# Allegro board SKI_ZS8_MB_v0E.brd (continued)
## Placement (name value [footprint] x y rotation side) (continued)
PR73  63.4k/f_4  [RC0402]  147.95 7.37 180 top
PR74  *short_6  [SHORT0603]  143.13 6.98 90 top
PR75  *4.7_6  [RC0603]  131.06 6.86 90 top
PR76  36.5k/f_4  [RC0402]  197.08 103.02 90 bottom
PR77  665k/f_4  [RC0402]  198.15 103.05 90 bottom
PR78  *90.9k/f_4  [RC0402]  199.24 103.07 90 bottom
PR79  2m/f_4  [RC0402]  204.34 102.87 0 bottom
PR80  30k/f_4  [RC0402]  200.38 102.77 270 bottom
PR81  39k/f_4  [RC0402]  201.42 102.36 270 bottom
PR82  10k/f_4  [RC0402]  204.34 101.73 0 bottom
PR83  *short_4  [SHORT0402]  194.92 101.7 270 bottom
PR84  100k/f_4  [RC0402]  195.94 101.7 270 bottom
PR85  20k/f_4  [RC0402]  197.08 100.91 270 bottom
PR86  100k/f_4  [RC0402]  198.17 101 270 bottom
PR87  150k/f_4  [RC0402]  199.26 100.99 270 bottom
PR88  2m/f_4  [RC0402]  200.41 100.69 90 bottom
PR89  374k/f_4  [RC0402]  201.42 100.25 270 bottom
PR90  *0_4  [RC0402]  195.45 100.08 0 bottom
PR91  16.9k/f_4  [RC0402]  204.88 100.08 90 bottom
PR92  *100k/f_4  [RC0402]  195.45 99.06 0 bottom
PR93  22_8  [RC0805]  66.93 98.93 180 bottom
PR94  *short_4  [SHORT0402]  204.47 98.4 0 bottom
PR95  *100k/f_4  [RC0402]  195.45 98.04 0 bottom
PR96  *10_4  [RC0402]  206.65 97.67 0 bottom
PR97  *short_4  [SHORT0402]  204.47 97.33 0 bottom
PR98  *short_4  [SHORT0402]  204.34 96.27 0 bottom
PR99  100k/f_4  [RC0402]  195.33 95.83 0 bottom
PR100  *short_4  [SHORT0402]  204.34 95.15 0 bottom
PR101  22_8  [RC0805]  66.93 95 180 bottom
PR102  22_8  [RC0805]  80.9 94.87 270 bottom
PR103  *short_4  [SHORT0402]  195.33 94.67 0 bottom
PR104  *10_4  [RC0402]  205.89 93.5 90 bottom
PR105  1_6  [RC0603]  195.07 93.47 0 bottom
PR106  *100k/f_6  [RC0603]  74.17 92.84 180 bottom
PR107  4.99k/f_4  [RC0402]  201.55 92.58 180 bottom
PR108  *short_4  [SHORT0402]  197.23 91.95 90 bottom
PR109  *short_4  [SHORT0402]  198.37 91.95 90 bottom
PR110  *short_4  [SHORT0402]  199.52 91.95 90 bottom
PR111  10k/f_4  [RC0402]  201.55 91.57 0 bottom
PR112  4.75k/f_4  [RC0402]  201.55 90.55 180 bottom
PR113  1m_4  [RC0402]  74.42 90.3 180 bottom
PR114  1m_4  [RC0402]  69.98 89.79 0 bottom
PR115  130/f_4  [RC0402]  197.23 89.79 270 bottom
PR116  *75/f_4  [RC0402]  198.37 89.79 270 bottom
PR117  56_4  [RC0402]  199.52 89.79 270 bottom
PR118  *1m_4  [RC0402]  73.85 88.71 90 bottom
PR119  1m_4  [RC0402]  69.98 88.65 180 bottom
PR120  30k/f_4  [RC0402]  66.67 88.27 90 bottom
PR121  *100k_4  [RC0402]  73.85 86.68 270 bottom
PR122  *0_4  [RC0402]  74.87 86.68 90 bottom
PR123  34k/f_4  [RC0402]  67.18 86.61 180 bottom
PR124  100k_4  [RC0402]  56.13 86.11 0 bottom
PR125  *100k_4  [RC0402]  74.36 85.16 0 bottom
PR126  *short_4  [SHORT0402]  56.13 84.96 0 bottom
PR127  *100k_4  [RC0402]  60.58 84.96 180 bottom
PR128  *1m_4  [RC0402]  69.85 83.06 90 bottom
PR129  *1m_4  [RC0402]  70.99 83.06 270 bottom
PR130  *22_8  [RC0805]  73.47 82.62 180 bottom
PR131  *short_8  [SHORT0805]  74.42 76.96 90 bottom
PR132  1.47k/f_4  [RC0402]  163.96 67.69 90 bottom
PR133  200k/f_4  [RC0402]  165.1 67.69 90 bottom
PR134  200k/f_4  [RC0402]  166.24 67.69 270 bottom
PR135  *4.7_6  [RC0603]  44.3 64.16 90 bottom
PR136  *4.7_6  [RC0603]  65.91 63.25 90 bottom
PR137  82k/f_4  [RC0402]  42.75 63.37 90 bottom
PR138  *4.7_6  [RC0603]  56.69 62.84 90 bottom
PR139  11k/f_4  [RC0402]  42.29 61.72 0 bottom
PR140  *short_6  [SHORT0603]  48.69 60.76 90 bottom
PR141  200k_6  [RC0603]  161.04 60.33 270 bottom
PR142  *short_6  [SHORT0603]  54.76 59.36 180 bottom
PR143  *short_6  [SHORT0603]  161.29 56.64 270 bottom
PR144  1m_6  [RC0603]  158.62 53.09 180 bottom
PR145  22_8  [RC0805]  50.8 48.34 90 bottom
PR146  *short_4  [SHORT0402]  179.96 47.62 0 bottom
PR147  *short_4  [SHORT0402]  65.53 47.12 90 bottom
PR148  10k/f_4  [RC0402]  66.55 47.12 90 bottom
PR149  5.1k/f_4  [RC0402]  67.56 47.12 90 bottom
PR150  0.01/f_0612  [RC3216]  183.13 46.99 180 bottom
PR151  *short_4  [SHORT0402]  179.96 46.48 0 bottom
PR152  *100k_4  [RC0402]  80.01 37.34 90 bottom
PR153  34k/f_4  [RC0402]  82.17 25.53 90 bottom
PR154  33k/f_4  [RC0402]  131.32 15.49 90 bottom
PR155  100k_4  [RC0402]  153.8 13.97 180 bottom
PR156  10k_4  [RC0402]  147.45 13.21 270 bottom
PR157  *0_4  [RC0402]  148.46 13.21 270 bottom
PR158  100k/f_4  [RC0402]  149.48 13.21 90 bottom
PR159  0.01/f_0612  [RC3216]  123.06 12.06 0 bottom
PR160  100k_4  [RC0402]  157.35 12.06 270 bottom
PR161  *0_4  [RC0402]  154.56 10.16 180 bottom
PR162  *short_4  [SHORT0402]  151.41 10.13 180 bottom
PR163  *short_6  [SHORT0603]  142.54 9.4 180 bottom
PR164  *short_4  [SHORT0402]  151.41 9.12 180 bottom
PR165  *short_4  [SHORT0402]  153.67 8.64 90 bottom
PR166  *10k_4  [RC0402]  154.69 8.64 90 bottom
PR167  316k/f_4  [RC0402]  151.41 8.1 180 bottom
PR168  100k/f_4  [RC0402]  151.41 7.06 0 bottom
PR169  *100k_4  [RC0402]  151.41 6.05 0 bottom
PR170  10k_4  [RC0402]  149.35 5.08 180 bottom
PR171  10_6  [RC0603]  146.43 4.7 270 bottom
PR172  7.5_6  [RC0603]  147.7 4.7 270 bottom
PR173  *short_4  [SHORT0402]  142.62 3.94 180 bottom
PR174  *short_4  [SHORT0402]  142.62 2.92 180 bottom
PR175  *short_8  [SHORT0805]  86.55 26.23 0 bottom
PR176  *short_4  [SHORT0402]  150.28 14.87 180 bottom
PU1  csd97374cq4m  [SON8-4_5X3_5-5-9P-SMT]  185.28 98.26 0 top
PU2  nb671gq-z  [QFN14-3X3-4-16P]  46.08 62.43 90 top
PU3  nb670gq-z  [QFN14-3X3-4-16P]  55.27 60.76 90 top
PU4  tps51716rukr  [QFN20-3X3-4-26P]  195.28 60.76 90 top
PU5  tps51211dscr  [SON10-3X3-5-16P]  65.96 50.5 0 top
PU6  *cm1293a-04so  [SOT23-6-2_8-95-6P]  108.97 6.86 180 top
PU7  tps51624rsm  [QFN32-4X4-4-42P-1H]  199.62 96.29 0 bottom
PU8  g9661-25adjf12u  [SOP8-6-1_27-9P]  61.98 88.27 90 bottom
PU9  as393mtr-e1  [SOIC8-6-1_27]  164.59 62.23 0 bottom
PU10  g9661-25adjf12u  [SOP8-6-1_27-9P]  83.31 31.62 0 bottom
PU11  bq24737rgrr  [PVQFN20-3_5X3_5-5-25P]  147.45 9.14 0 bottom
Q1  fdv301n  [SOT23_213-3_3-2]  134.92 97.42 90 top
Q2  mmbt3904-7-f  [SOT23_213-3_3-2]  139.87 97.29 90 top
Q3  ap2331sa-7  [SOT23_213-3_3-2]  11.18 97.16 180 top
Q4  dtc144eu  [UMT_213-3-1_3]  24.32 83.99 270 top
Q5  2n7002dw  [SC70-2_1-65-6P]  20.07 93.09 270 top
Q6  bsn20  [SOT23_213-3_3-2]  12.45 89.66 270 top
Q7  bsn20  [SOT23_213-3_3-2]  16.13 89.66 270 top
Q8  *2n7002dw  [SC70-2_1-65-6P]  199.01 74.68 0 top
Q9  2n7002k  [SOT23_213-3_3-2]  13.59 73.63 0 top
Q10  *2n7002dw  [SC70-2_1-65-6P]  82.55 72.9 180 top
Q11  *2n7002dw  [SC70-2_1-65-6P]  82.55 70.1 180 top
Q12  mmbt3904  [SOT23_213-3_3-2]  208.15 63.88 270 top
Q13  *ao3413  [SOT23_213-3_3-2]  84.9 54.55 270 top
Q14  *2n7002k  [SOT23_213-3_3-2]  81.15 51.69 270 top
Q15  2n7002k  [SOT23_213-3_3-2]  28.19 33.15 0 top
Q16  2n7002k  [SOT23_213-3_3-2]  195.33 32.51 90 top
Q17  2n7002dw  [SC70-2_1-65-6P]  175.58 20.51 90 bottom
Q18  2n7002k  [SOT23_213-3_3-2]  11.57 89.15 0 bottom
Q19  ao3413  [SOT23_213-3_3-2]  199.26 82.3 180 bottom
Q20  2n7002k  [SOT23_213-3_3-2]  77.6 80.64 180 bottom
Q21  2n7002k  [SOT23_213-3_3-2]  199.26 78.61 0 bottom
Q22  *2n7002k  [SOT23_213-3_3-2]  185.67 54.86 270 bottom
Q23  2n7002dw  [SC70-2_1-65-6P]  32 27.3 180 bottom
Q24  2n7002k  [SOT23_213-3_3-2]  70.54 26.92 180 bottom
Q25  2n7002dw  [SC70-2_1-65-6P]  35.56 12.95 0 bottom
Q53  ao3413  [SOT23_213-3_3-2]  33.85 5.91 0 top
Q54  *dtc144eu  [UMT_213-3-1_3]  43.88 3.5 180 top
Q55  *dtc144eu  [UMT_213-3-1_3]  47.56 3.5 180 top
Q56  *2n7002k  [SOT23_213-3_3-2]  52.77 4 180 top
R1  *short_8  [SHORT0805]  95.38 100.46 180 top
R2  10k_4  [RC0402]  133.73 100.08 180 top
R3  1k_4  [RC0402]  137.41 98.81 90 top
R4  *0_4  [RC0402]  162.43 98.81 90 top
R5  *1k_4  [RC0402]  163.58 98.81 90 top
R6  *1k_4  [RC0402]  164.72 98.81 90 top
R7  *short_4  [SHORT0402]  127.42 98.31 90 top
R8  10k_4  [RC0402]  128.69 98.31 90 top
R9  *0_4  [RC0402]  123.36 97.67 180 top
R10  *short_8  [SHORT0805]  94.61 97.66 90 top
R11  *short_8  [SHORT0805]  96.65 97.66 270 top
R12  1k_4  [RC0402]  137.41 96.77 90 top
R13  0_4  [RC0402]  123.36 96.53 180 top
R14  10k_4  [RC0402]  18.87 96.16 0 top
R15  *10k_4  [RC0402]  148.34 96.14 90 top
R16  *0_4  [RC0402]  123.36 95.39 180 top
R17  *10k_4  [RC0402]  136.27 94.36 90 top
R18  10k_4  [RC0402]  96.27 93.98 90 top
R19  10k_4  [RC0402]  97.41 93.99 90 top
R20  *1k_4  [RC0402]  98.55 93.98 270 top
R21  10k_4  [RC0402]  99.69 93.98 90 top
R22  10k_4  [RC0402]  100.71 93.98 90 top
R23  *10k_4  [RC0402]  101.73 93.98 90 top
R24  2.2k_4  [RC0402]  93.85 93.71 90 top
R25  2.2k_4  [RC0402]  95.12 93.71 90 top
R26  *short_4  [SHORT0402]  140.59 93.34 90 top
R27  2.2k_4  [RC0402]  12.57 92.96 270 top
R28  10k_4  [RC0402]  137.54 92.96 90 top
R29  2.2k_4  [RC0402]  17.53 92.71 270 top
R30  51_4  [RC0402]  142.75 92.58 270 top
R31  *short_4  [SHORT0402]  143.89 92.58 270 top
R32  10k_4  [RC0402]  120.89 91.2 90 top
R33  10k_4  [RC0402]  122.03 91.2 90 top
R34  *0_4  [RC0402]  124.8 91.85 180 top
R35  *0_4  [RC0402]  124.8 90.65 180 top
R36  *0_4  [RC0402]  132.97 91.19 270 top
R37  10k_4  [RC0402]  136.14 91.19 270 top
R38  100/f_4  [RC0402]  140.08 91.19 90 top
R39  100/f_4  [RC0402]  141.48 91.19 270 top
R40  10k_4  [RC0402]  19.5 90.24 0 top
R41  1m_4  [RC0402]  114.67 90.97 180 top
R42  150_4  [RC0402]  143.26 90.93 0 top
R43  3.01k/f_4  [RC0402]  116.19 90.56 270 top
R44  *short_4  [SHORT0402]  117.36 90.56 270 top
R45  100k_4  [RC0402]  21.28 89.6 90 top
R46  10k_4  [RC0402]  82.62 87.95 90 top
R47  10k_4  [RC0402]  83.63 87.95 90 top
R48  10k_4  [RC0402]  84.65 87.95 90 top
R49  10k_4  [RC0402]  85.66 87.95 90 top
R50  10k_4  [RC0402]  86.68 87.95 90 top
R51  10k_4  [RC0402]  87.7 87.95 90 top
R52  2.2k_4  [RC0402]  13.84 87 180 top
R53  2.2k_4  [RC0402]  16.51 87 0 top
R54  *51_4  [RC0402]  160.91 86.74 270 top
R55  *0_4  [RC0402]  161.93 86.74 270 top
R56  *1k_4  [RC0402]  162.94 86.74 270 top
R57  *1k_4  [RC0402]  163.96 86.74 270 top
R58  10k_4  [RC0402]  80.71 85.79 180 top
R59  *100/f_4  [RC0402]  12.32 84.96 90 top
R60  *10k_4  [RC0402]  80.71 84.78 180 top
R61  10k_4  [RC0402]  83.38 84.78 0 top
R62  10k_4  [RC0402]  86.05 84.78 0 top
R63  *10k_4  [RC0402]  80.71 83.76 180 top
R64  10k_4  [RC0402]  83.38 83.76 0 top
R65  10k_4  [RC0402]  86.05 83.76 0 top
R66  10k_4  [RC0402]  88.71 83.76 180 top
R67  *0_8  [RC0805]  199.2 81.73 0 top
R68  56_4  [RC0402]  143.26 82.8 180 top
R69  62_4  [RC0402]  145.54 82.8 0 top
R70  *10k_4  [RC0402]  80.71 82.74 180 top
R71  10k_4  [RC0402]  83.38 82.74 180 top
R72  10k_4  [RC0402]  86.05 82.74 180 top
R73  *100/f_4  [RC0402]  12.32 82.55 90 top
R74  10k_4  [RC0402]  80.58 81.73 0 top
R75  *short_4  [SHORT0402]  83.38 81.73 0 top
R76  10k_4  [RC0402]  85.79 81.73 180 top
R77  *short_4  [SHORT0402]  143.38 81.66 180 top
R78  130/f_4  [RC0402]  145.54 81.66 180 top
R79  100k_4  [RC0402]  199.39 83.44 0 top
R80  st@10k_4  [RC0402]  80.46 80.71 180 top
R81  10k_4  [RC0402]  83.38 80.71 0 top
R82  10k_4  [RC0402]  85.41 80.71 180 top
R83  43_4  [RC0402]  143.26 80.52 180 top
R84  75_4  [RC0402]  145.54 80.52 180 top
R85  *0_4  [RC0402]  78.93 80.46 270 top
R86  *0_4  [RC0402]  80.84 79.7 180 top
R87  st@10k_4  [RC0402]  83.38 79.7 180 top
R88  *1k_4  [RC0402]  86.05 79.7 0 top
R89  100k_4  [RC0402]  21.21 79.63 270 top
R90  *short_6  [SHORT0603]  199.84 79.57 0 top
R91  *short_4  [SHORT0402]  143.64 79.5 180 top
R92  *100/f_4  [RC0402]  12.32 78.99 90 top
R93  10k_4  [RC0402]  80.84 78.68 0 top
R94  10k_4  [RC0402]  83.38 78.68 180 top
R95  10k_4  [RC0402]  85.92 78.68 180 top
R96  *1k_4  [RC0402]  142.11 78.36 180 top
R97  *st@10k_4  [RC0402]  80.84 77.66 180 top
R98  10k_4  [RC0402]  83.38 77.66 180 top
R99  10k_4  [RC0402]  85.92 77.66 0 top
R100  *1k_4  [RC0402]  142.88 77.34 180 top
R101  *short_6  [SHORT0603]  202.89 78.68 0 top
R102  *short_8  [SHORT0805]  20.19 77.22 180 top
R103  1k_4  [RC0402]  145.03 77.22 0 top
R104  *1k_4  [RC0402]  147.19 77.22 180 top
R105  *1k_4  [RC0402]  149.3 76.9 0 top
R106  *1k_4  [RC0402]  151.46 76.9 180 top
R107  *0_4  [RC0402]  88.08 77.16 90 top
R108  0_4  [RC0402]  89.09 77.16 90 top
R109  *0_4  [RC0402]  85.92 76.65 180 top
R110  *100/f_4  [RC0402]  12.32 76.45 90 top
R111  49.9/f_4  [RC0402]  142.11 76.07 180 top
R112  *1k_4  [RC0402]  144.27 76.07 180 top
R113  10k_4  [RC0402]  85.92 75.63 180 top
R114  10k_4  [RC0402]  88.71 75.63 180 top
R115  *0_4  [RC0402]  81.47 75.38 0 top
R116  2.2k_4  [RC0402]  84.14 75.25 90 top
R117  51_4  [RC0402]  149.35 74.8 0 top
R118  *51_4  [RC0402]  151.51 74.8 180 top
R119  *0_4  [RC0402]  85.92 74.62 0 top
R120  *0_4  [RC0402]  88.71 74.62 0 top
R121  *4.7k_4  [RC0402]  79.38 73.79 0 top
R122  51_4  [RC0402]  142.11 73.79 0 top
R123  51_4  [RC0402]  144.27 73.79 180 top
R124  51_4  [RC0402]  146.43 73.79 0 top
R125  *1k_4  [RC0402]  148.59 73.79 180 top
R126  2.2k_4  [RC0402]  85.66 73.47 0 top
R127  10k_4  [RC0402]  88.71 73.6 180 top
R128  100k_4  [RC0402]  31.75 78.93 180 top
R129  *100k_4  [RC0402]  33.91 78.93 0 top
R130  2.2k_4  [RC0402]  79.38 72.39 180 top
R131  *4.7k_4  [RC0402]  85.66 72.08 180 top
R132  10k_4  [RC0402]  88.71 72.58 180 top
R133  0_4  [RC0402]  21.01 70.87 180 top
R134  *2.2k_4  [RC0402]  78.99 70.61 180 top
R135  0_4  [RC0402]  85.85 70.61 0 top
R136  *10k_4  [RC0402]  88.39 70.48 180 top
R137  *100k_4  [RC0402]  31.75 77.66 180 top
R138  100k_4  [RC0402]  33.91 77.66 0 top
R139  0_4  [RC0402]  78.99 69.6 180 top
R140  *2.2k_4  [RC0402]  85.85 69.6 0 top
R141  10k_4  [RC0402]  88.39 69.47 180 top
R142  220k/f_4  [RC0402]  149.1 69.09 270 top
R143  *short_8  [SHORT0805]  24.13 69.47 0 top
R144  10k_4  [RC0402]  83.44 68.2 180 top
R145  2.2k_4  [RC0402]  85.85 68.2 180 top
R146  10k_4  [RC0402]  87.91 68.2 180 top
R147  *51_4  [RC0402]  141.61 67.94 90 top
R148  *10k_4  [RC0402]  83.44 67.18 180 top
R149  10k_4  [RC0402]  85.85 67.18 180 top
R150  *short_8  [SHORT0805]  24.13 67.31 0 top
R151  *10k_4  [RC0402]  83.44 66.17 180 top
R152  10k_4  [RC0402]  85.85 66.17 180 top
R153  10k_4  [RC0402]  88.01 66.17 180 top
R154  *short_4  [SHORT0402]  185.42 65.91 270 top
R155  10k_4  [RC0402]  85.85 65.15 180 top
R156  10k_4  [RC0402]  88.01 65.15 180 top
R157  10k_4  [RC0402]  204.47 65.15 90 top
R158  10k_4  [RC0402]  205.61 65.15 270 top
R159  *short_8  [SHORT0805]  202.82 64.52 270 top
R160  *10k_4  [RC0402]  83.44 64.01 180 top
R161  10k_4  [RC0402]  85.85 64.01 180 top
R163  *0_4  [RC0402]  20.41 61.97 180 top
R164  10k_4  [RC0402]  85.85 62.86 180 top
R165  1k_4  [RC0402]  204.47 62.86 90 top
R166  *0_4  [RC0402]  83.44 61.59 0 top
R167  10k_4  [RC0402]  85.85 61.59 180 top
R168  *short_4  [SHORT0402]  23.13 61.41 90 top
R169  100k_4  [RC0402]  97.1 60.81 180 top
R171  *0_4  [RC0402]  20.41 60.95 180 top
R172  10k_4  [RC0402]  97.1 59.79 180 top
R173  10m_4  [RC0402]  90.3 59.69 0 top
R174  20k/f_4  [RC0402]  94.11 59.69 0 top
R175  15_4  [RC0402]  71.12 59.56 270 top
R176  15_4  [RC0402]  73.41 59.56 270 top
R177  *1k_4  [RC0402]  74.55 59.56 270 top
R178  330k_4  [RC0402]  98.68 58.93 90 top
R179  330k_4  [RC0402]  99.69 58.93 90 top
R180  33_4  [RC0402]  100.71 58.93 90 top
R181  0_4  [RC0402]  96.65 56.13 90 top
R182  *short_4  [SHORT0402]  97.79 56.13 90 top
R183  *0_4  [RC0402]  98.81 56.13 90 top
R184  0_4  [RC0402]  99.82 56.13 90 top
R185  33_4  [RC0402]  101.85 56.13 90 top
R186  49.9/f_4  [RC0402]  103.33 56.06 270 top
R187  49.9/f_4  [RC0402]  104.34 56.06 270 top
R188  tpm@22_4  [RC0402]  105.56 56.03 270 top
R189  100k_4  [RC0402]  90.93 55.5 180 top
R190  *0_4  [RC0402]  96.65 53.85 270 top
R191  100k_4  [RC0402]  99.82 53.72 270 top
R192  *10k_4  [RC0402]  90.93 53.34 180 top
R193  *0_4  [RC0402]  90.93 52.32 180 top
R194  *0_6  [RC0603]  36.7 44.2 180 top
R195  *0_6  [RC0603]  39.37 44.2 180 top
R196  *0_6  [RC0603]  34.04 42.93 180 top
R197  *0_6  [RC0603]  36.7 42.93 180 top
R198  *0_6  [RC0603]  39.37 42.93 180 top
R199  *short_4  [SHORT0402]  202.63 40.96 180 top
R200  *short_4  [SHORT0402]  21.34 42.55 0 top
R201  *10k_4  [RC0402]  202.63 39.82 180 top
R202  *short_4  [SHORT0402]  179.96 40.26 90 top
R203  2.2_6  [RC0603]  47.5 39.62 270 top
R204  240/f_4  [RC0402]  146.05 39.27 180 top
R205  *short_4  [SHORT0402]  202.63 37.53 180 top
R206  240/f_4  [RC0402]  107.87 38.99 90 top
R207  80.6/f_4  [RC0402]  144.9 37.51 180 top
R208  *short_4  [SHORT0402]  60.58 37.34 0 top
R209  80.6/f_4  [RC0402]  107.7 37.34 0 top
R210  10k_4  [RC0402]  202.63 36.39 0 top
R211  80.6/f_4  [RC0402]  144.9 36.5 180 top
R212  80.6/f_4  [RC0402]  107.7 36.2 0 top
R213  *short_4  [SHORT0402]  179.96 35.81 90 top
R214  100k_4  [RC0402]  27.43 35.69 180 top
R215  80.6/f_4  [RC0402]  144.9 35.48 180 top
R216  80.6/f_4  [RC0402]  107.7 35.05 0 top
R217  240/f_4  [RC0402]  127.64 34.92 270 top
R218  240/f_4  [RC0402]  146.55 34.84 270 top
R219  240/f_4  [RC0402]  89.41 34.34 180 top
R220  *short_4  [SHORT0402]  21.59 33.91 180 top
R221  240/f_4  [RC0402]  108.97 33.53 90 top
R222  240/f_4  [RC0402]  126.82 33.32 180 top
R223  240/f_4  [RC0402]  89.41 33.19 180 top
R224  *short_4  [SHORT0402]  77.57 33.15 270 top
R225  *short_4  [SHORT0402]  78.61 33.15 270 top
R226  *100k_4  [RC0402]  32.13 32.51 270 top
R227  1m_4  [RC0402]  197.81 32.2 270 top
R228  *short_4  [SHORT0402]  60.45 32.26 0 top
R229  0_4  [RC0402]  194.76 29.66 0 top
R230  *short_4  [SHORT0402]  29.59 30.1 270 top
R231  54.9/f_4  [RC0402]  129.54 29.38 270 top
R232  54.9/f_4  [RC0402]  130.68 29.38 270 top
R233  54.9/f_4  [RC0402]  131.82 29.38 270 top
R234  54.9/f_4  [RC0402]  132.97 29.38 270 top
R235  54.9/f_4  [RC0402]  134.11 29.38 270 top
R236  37.4/f_4  [RC0402]  135.25 29.38 270 top
R237  37.4/f_4  [RC0402]  136.27 29.38 270 top
R238  80.6/f_4  [RC0402]  137.28 29.38 270 top
R239  80.6/f_4  [RC0402]  138.3 29.38 270 top
R240  54.9/f_4  [RC0402]  139.32 29.38 270 top
R241  54.9/f_4  [RC0402]  140.33 29.38 270 top
R242  54.9/f_4  [RC0402]  141.35 29.38 270 top
R243  54.9/f_4  [RC0402]  142.36 29.38 270 top
R244  54.9/f_4  [RC0402]  143.38 29.38 270 top
R245  54.9/f_4  [RC0402]  147.19 29.38 270 top
R246  54.9/f_4  [RC0402]  148.21 29.38 270 top
R247  54.9/f_4  [RC0402]  149.35 29.38 270 top
R248  54.9/f_4  [RC0402]  150.49 29.38 270 top
R249  54.9/f_4  [RC0402]  151.63 29.38 270 top
R250  37.4/f_4  [RC0402]  152.78 29.38 270 top
R251  37.4/f_4  [RC0402]  153.79 29.38 270 top
R252  80.6/f_4  [RC0402]  154.81 29.38 270 top
R253  80.6/f_4  [RC0402]  155.83 29.38 270 top
R254  54.9/f_4  [RC0402]  156.84 29.38 270 top
R255  54.9/f_4  [RC0402]  157.86 29.38 270 top
R256  54.9/f_4  [RC0402]  158.87 29.38 270 top
R257  54.9/f_4  [RC0402]  159.89 29.38 270 top
R258  54.9/f_4  [RC0402]  160.91 29.38 270 top
R259  54.9/f_4  [RC0402]  92.72 29.26 270 top
R260  54.9/f_4  [RC0402]  93.86 29.26 270 top
R261  54.9/f_4  [RC0402]  95 29.26 270 top
R262  54.9/f_4  [RC0402]  96.15 29.26 270 top
R263  54.9/f_4  [RC0402]  97.29 29.26 270 top
R264  37.4/f_4  [RC0402]  98.43 29.26 270 top
R265  37.4/f_4  [RC0402]  99.45 29.26 270 top
R266  80.6/f_4  [RC0402]  100.46 29.26 270 top
R267  80.6/f_4  [RC0402]  101.48 29.26 270 top
R268  54.9/f_4  [RC0402]  102.5 29.26 270 top
R269  54.9/f_4  [RC0402]  103.51 29.26 270 top
R270  54.9/f_4  [RC0402]  104.53 29.26 270 top
R271  54.9/f_4  [RC0402]  105.54 29.26 270 top
R272  54.9/f_4  [RC0402]  106.56 29.26 270 top
R273  54.9/f_4  [RC0402]  110.07 29.26 270 top
R274  54.9/f_4  [RC0402]  111.08 29.26 270 top
R275  54.9/f_4  [RC0402]  112.23 29.26 270 top
R276  54.9/f_4  [RC0402]  113.37 29.26 270 top
R277  54.9/f_4  [RC0402]  114.51 29.26 270 top
R278  37.4/f_4  [RC0402]  115.65 29.26 270 top
R279  37.4/f_4  [RC0402]  116.67 29.26 270 top
R280  80.6/f_4  [RC0402]  117.69 29.26 270 top
R281  80.6/f_4  [RC0402]  118.7 29.26 270 top
R282  54.9/f_4  [RC0402]  119.72 29.26 270 top
R283  54.9/f_4  [RC0402]  120.73 29.26 270 top
R284  54.9/f_4  [RC0402]  121.75 29.26 270 top
R285  54.9/f_4  [RC0402]  122.77 29.26 270 top
R286  54.9/f_4  [RC0402]  123.78 29.26 270 top
R287  47k_4  [RC0402]  40.89 29.08 90 top
R288  *short_4  [SHORT0402]  24 28.96 270 top
R289  *short_4  [SHORT0402]  16.96 28.77 270 top
R290  *short_8  [SHORT0805]  202.25 27.63 0 top
R291  4.7k_4  [RC0402]  40.51 27.43 180 top
R292  20k/f_4  [RC0402]  35.56 26.8 90 top
R293  39.2k/f_4  [RC0402]  36.7 26.8 90 top
R294  *short_6  [SHORT0603]  67.87 23.34 0 top
R295  10k_4  [RC0402]  41.78 23.24 0 top
R296  *1k_4  [RC0402]  22.23 21.97 270 top
R297  4.7k_4  [RC0402]  27.3 21.97 180 top
R298  tpm@0_6  [RC0603]  68.58 21.72 0 top
R299  *tpm@4.7k_4  [RC0402]  73.02 21.34 270 top
R300  *tpm@0_4  [RC0402]  74.17 21.34 270 top
R301  *tpm@10k_4  [RC0402]  75.56 21.34 270 top
R302  4.7k_4  [RC0402]  27.3 20.95 180 top
R303  *tpm@0_6  [RC0603]  68.58 20.45 0 top
R304  *1k_4  [RC0402]  22.23 19.94 270 top
R305  56/f_4  [RC0402]  27.3 19.81 180 top
R308  *short_8  [SHORT0805]  201.87 21.4 270 top
R309  56/f_4  [RC0402]  27.3 18.67 180 top
R310  *10k_4  [RC0402]  39.37 16.76 90 top
R311  *0_4  [RC0402]  200.53 16.38 0 top
R312  *0_4  [RC0402]  200.53 15.11 0 top
R313  *short_6  [SHORT0603]  34.92 13.34 90 top
R314  *short_6  [SHORT0603]  36.32 13.34 90 top
R315  *short_4  [SHORT0402]  201.36 9.08 180 top
R316  *short_4  [SHORT0402]  22.23 11.81 90 top
R317  *short_6  [SHORT0603]  28.32 11.43 90 top
R318  *10k_4  [RC0402]  201.36 11.24 180 top
R319  *short_4  [SHORT0402]  201.36 10.23 180 top
R320  *short_4  [SHORT0402]  18.14 9.68 90 top
R321  *short_4  [SHORT0402]  6.35 9.27 90 top
R322  0_6  [RC0603]  19.05 7.24 180 top
R323  *0_6  [RC0603]  29.02 6.29 270 top
R325  *short_4  [SHORT0402]  37.91 6.54 90 top
R326  0_6  [RC0603]  19.05 5.84 180 top
R327  0_6  [RC0603]  19.05 4.57 180 top
R328  0_6  [RC0603]  19.05 3.17 180 top
R329  *0_6  [RC0603]  104.14 96.01 180 bottom
R330  10k_4  [RC0402]  92.96 94.61 180 bottom
R331  100k_4  [RC0402]  27.22 85.36 0 top
R332  *short_6  [SHORT0603]  90.3 94.08 180 bottom
R333  *short_6  [SHORT0603]  108.84 93.85 90 bottom
R334  10k_4  [RC0402]  92.96 93.6 180 bottom
R335  100k_4  [RC0402]  97.66 93.6 90 bottom
R336  3.01k/f_4  [RC0402]  105.18 93.6 90 bottom
R337  *short_4  [SHORT0402]  106.2 93.6 90 bottom
R338  8.2k_4  [RC0402]  107.57 93.6 270 bottom
R339  *short_6  [SHORT0603]  111 93.09 180 bottom
R340  0_4  [RC0402]  26.56 83.66 90 top
R341  0_4  [RC0402]  27.73 83.66 90 top
R342  3.01k/f_4  [RC0402]  114.3 92.08 180 bottom
R343  1m_4  [RC0402]  15.23 88.41 180 bottom
R344  10k_4  [RC0402]  82.62 87.95 90 bottom
R345  *1k_4  [RC0402]  83.63 87.95 270 bottom
R346  2.2k_4  [RC0402]  84.65 87.95 90 bottom
R347  2.2k_4  [RC0402]  85.66 87.95 90 bottom
R348  *short_4  [SHORT0402]  10.67 86.82 180 bottom
R349  20k_4  [RC0402]  13.97 86.69 0 bottom
R350  470_4  [RC0402]  14.1 85.6 0 bottom
R351  10k_4  [RC0402]  80.71 84.78 180 bottom
R352  10k_4  [RC0402]  83.38 84.78 0 bottom
R353  10k_4  [RC0402]  86.05 84.78 180 bottom
R354  470_4  [RC0402]  14.1 84.45 0 bottom
R355  10k_4  [RC0402]  80.71 83.76 180 bottom
R356  10k_4  [RC0402]  83.38 83.76 180 bottom
R357  10k_4  [RC0402]  86.05 83.76 180 bottom
R358  24.9/f_4  [RC0402]  110.87 83.57 180 bottom
R359  470_4  [RC0402]  14.1 83.19 0 bottom
R360  10k_4  [RC0402]  83.38 82.74 180 bottom
R361  10k_4  [RC0402]  86.05 82.74 180 bottom
R362  *10k_4  [RC0402]  80.71 82.36 180 bottom
R363  470_4  [RC0402]  14.1 82.04 0 bottom
R364  10k_4  [RC0402]  83.38 81.73 180 bottom
R365  10k_4  [RC0402]  85.79 81.73 0 bottom
R366  *short_6  [SHORT0603]  110.96 81.6 270 bottom
R367  *short_4  [SHORT0402]  83.38 80.71 0 bottom
R368  10k_4  [RC0402]  85.41 80.71 0 bottom
R369  10k_4  [RC0402]  89.22 80.71 0 bottom
R370  10k_4  [RC0402]  80.58 80.46 0 bottom
R371  8.2k_4  [RC0402]  83.38 79.7 180 bottom
R372  10k_4  [RC0402]  86.05 79.7 180 bottom
R373  470_4  [RC0402]  14.1 79.63 0 bottom
R374  10k_4  [RC0402]  88.08 78.81 0 bottom
R375  10k_4  [RC0402]  90.36 78.81 0 bottom
R376  0_4  [RC0402]  83.38 78.68 180 bottom
R377  st@10k_4  [RC0402]  85.92 78.68 180 bottom
R378  10k_4  [RC0402]  195.58 78.61 270 bottom
R379  *0_4  [RC0402]  196.6 78.61 270 bottom
R380  470_4  [RC0402]  14.1 78.49 0 bottom
R381  *short_6  [SHORT0603]  105.27 78.48 90 bottom
R382  *short_6  [SHORT0603]  109.49 77.89 90 bottom
R383  10k_4  [RC0402]  83.38 77.66 180 bottom
R384  10k_4  [RC0402]  85.92 77.66 180 bottom
R385  470_4  [RC0402]  14.1 77.09 0 bottom
R386  *0_6  [RC0603]  107.28 76.9 180 bottom
R387  *10k_4  [RC0402]  197.36 76.2 0 bottom
R388  *2.2k_4  [RC0402]  199.9 76.2 180 bottom
R389  470_4  [RC0402]  14.1 75.95 0 bottom
R390  10k_4  [RC0402]  85.92 75.63 180 bottom
R391  10k_4  [RC0402]  88.71 75.63 180 bottom
R392  *0_6  [RC0603]  107.25 75.48 180 bottom
R393  *0_4  [RC0402]  81.79 75.44 90 bottom
R394  0_4  [RC0402]  83 75.25 90 bottom
R395  10k_4  [RC0402]  84.14 75.25 90 bottom
R396  *short_6  [SHORT0603]  109.69 75.3 90 bottom
R397  0_4  [RC0402]  197.76 75.18 0 bottom
R398  *2.2k_4  [RC0402]  199.8 75.18 180 bottom
R399  10k_4  [RC0402]  88.71 74.62 180 bottom
R400  0_4  [RC0402]  197.99 74.17 0 bottom
R401  *0_6  [RC0603]  105.2 73.85 270 bottom
R402  *short_6  [SHORT0603]  74.3 73.66 90 bottom
R403  8.2k_4  [RC0402]  88.71 73.6 0 bottom
R404  *short_6  [SHORT0603]  106.37 73.27 90 bottom
R405  *short_6  [SHORT0603]  107.53 73.27 90 bottom
R406  10k_4  [RC0402]  88.71 72.58 180 bottom
R407  0_6  [RC0603]  113.73 72.08 270 bottom
R408  *0_6  [RC0603]  115 72.08 270 bottom
R409  *1k_4  [RC0402]  83.82 71.88 180 bottom
R410  1k_4  [RC0402]  86.23 71.88 0 bottom
R411  *short_4  [SHORT0402]  202.06 74.17 0 bottom
R412  *10k_4  [RC0402]  83.82 70.36 180 bottom
R413  10k_4  [RC0402]  86.11 70.23 180 bottom
R414  *short_4  [SHORT0402]  202.06 73.15 0 bottom
R415  *short_4  [SHORT0402]  202.06 72.14 0 bottom
R416  *short_4  [SHORT0402]  84.07 68.71 270 bottom
R417  *10k_4  [RC0402]  85.6 68.71 90 bottom
R418  10k_4  [RC0402]  86.61 68.71 90 bottom
R419  *short_4  [SHORT0402]  202.06 71.12 0 bottom
R420  *1k_4  [RC0402]  74.42 67.56 270 bottom
R421  *1k_4  [RC0402]  75.69 67.56 270 bottom
R422  *0_4  [RC0402]  76.96 67.56 270 bottom
R423  *0_4  [RC0402]  78.23 67.56 270 bottom
R424  15_4  [RC0402]  18.03 67.44 180 bottom
R425  10k_4  [RC0402]  83.44 67.18 180 bottom
R426  15_4  [RC0402]  18.03 66.42 180 bottom
R427  *10k_4  [RC0402]  83.44 66.17 180 bottom
R428  *8.2k_4  [RC0402]  83.44 65.15 180 bottom
R429  8.2k_4  [RC0402]  85.79 65.22 180 bottom
R430  *1k_4  [RC0402]  74.42 64.52 90 bottom
R431  *1k_4  [RC0402]  75.69 64.52 90 bottom
R432  *1k_4  [RC0402]  76.96 64.52 90 bottom
R433  10k_4  [RC0402]  20.45 64.39 180 bottom
R434  *short_8  [SHORT0805]  81.79 63.5 0 bottom
R435  *short_6  [SHORT0603]  168.15 63.25 270 bottom
R436  10k_4  [RC0402]  99.06 62.86 180 bottom
R437  22.6/f_4  [RC0402]  104.65 62.81 180 bottom
R438  120/f_4  [RC0402]  136.35 62.26 90 bottom
R439  200/f_4  [RC0402]  137.36 62.26 90 bottom
R440  100/f_4  [RC0402]  138.38 62.26 90 bottom
R441  *1k_4  [RC0402]  74.42 62.23 270 bottom
R442  *1k_4  [RC0402]  75.69 62.23 270 bottom
R443  *1k_4  [RC0402]  76.96 62.23 270 bottom
R444  10k_4  [RC0402]  99.06 61.85 180 bottom
R445  *10k_4  [RC0402]  93.24 60.25 180 bottom
R446  *short_4  [SHORT0402]  20.62 59.56 0 bottom
R447  *short_4  [SHORT0402]  71.12 59.44 270 bottom
R448  *short_4  [SHORT0402]  73.41 59.56 270 bottom
R449  15_4  [RC0402]  74.55 59.56 270 bottom
R450  *100k_4  [RC0402]  83.82 59.44 90 bottom
R451  10k_4  [RC0402]  85.85 59.44 90 bottom
R452  *10k_4  [RC0402]  94.77 59.44 270 bottom
R453  *short_6  [SHORT0603]  104.6 59.21 90 bottom
R454  22_4  [RC0402]  105.97 58.98 270 bottom
R455  *10k_4  [RC0402]  93.24 58.93 180 bottom
R456  *short_4  [SHORT0402]  99.21 58.93 270 bottom
R457  33_4  [RC0402]  98.04 58.9 90 bottom
R458  0_6  [RC0603]  82.55 58.67 270 bottom
R459  20k/f_4  [RC0402]  103 58.42 0 bottom
R460  22_4  [RC0402]  108.53 58.29 180 bottom
R461  *short_8  [SHORT0805]  124.68 58.18 270 bottom
R462  *short_8  [SHORT0805]  127.72 58.18 270 bottom
R463  *short_4  [SHORT0402]  77.09 57.91 0 bottom
R464  *short_4  [SHORT0402]  93.24 57.91 0 bottom
R465  1m_4  [RC0402]  96.42 57.84 180 bottom
R466  15_4  [RC0402]  17.4 57.4 180 bottom
R467  24.9/f_4  [RC0402]  110.52 56.74 90 bottom
R468  10/f_4  [RC0402]  112.55 56.74 270 bottom
R469  15_4  [RC0402]  17.4 56.39 180 bottom
R470  33_4  [RC0402]  98.42 56.26 90 bottom
R471  24.9/f_4  [RC0402]  145.4 55.53 90 bottom
R472  10/f_4  [RC0402]  147.69 55.53 270 bottom
R473  *short_4  [SHORT0402]  183.01 55.37 90 bottom
R474  *10k_4  [RC0402]  188.09 55.5 90 bottom
R475  15_4  [RC0402]  76.71 55.25 270 bottom
R476  8.2k/f_4  [RC0402]  110.52 54.71 90 bottom
R477  8.2k/f_4  [RC0402]  112.55 54.71 270 bottom
R478  *1k_4  [RC0402]  77.09 53.59 180 bottom
R479  8.2k/f_4  [RC0402]  145.42 53.21 90 bottom
R480  8.2k/f_4  [RC0402]  146.56 53.21 270 bottom
R481  *0_4  [RC0402]  20.57 52.96 180 bottom
R482  10k_4  [RC0402]  77.09 52.45 0 bottom
R483  *short_8  [SHORT0805]  201.87 51.88 180 bottom
R484  10k_4  [RC0402]  88.14 51.82 270 bottom
R485  10k_4  [RC0402]  93.98 51.82 270 bottom
R486  15_4  [RC0402]  69.72 51.44 270 bottom
R487  *short_4  [SHORT0402]  76.58 49.78 90 bottom
R488  *0_4  [RC0402]  201.55 49.4 0 bottom
R489  *short_4  [SHORT0402]  69.72 49.38 90 bottom
R490  47k_4  [RC0402]  20.57 49.02 0 bottom
R491  *0_4  [RC0402]  201.55 48.39 0 bottom
R492  *short_4  [SHORT0402]  82.17 46.99 270 bottom
R493  *0_4  [RC0402]  30.73 46.1 90 bottom
R494  *0_4  [RC0402]  31.75 46.1 90 bottom
R495  *0_4  [RC0402]  32.77 46.1 90 bottom
R496  *0_4  [RC0402]  33.78 46.1 90 bottom
R497  *0_4  [RC0402]  34.8 46.1 90 bottom
R498  *0_4  [RC0402]  35.81 46.1 90 bottom
R499  *0_4  [RC0402]  36.83 46.1 90 bottom
R500  *0_4  [RC0402]  37.85 46.1 90 bottom
R501  1k_4  [RC0402]  83.69 45.08 0 bottom
R502  15_4  [RC0402]  18.29 44.58 180 bottom
R503  0_4  [RC0402]  202.06 44.32 0 bottom
R504  15_4  [RC0402]  18.29 43.56 180 bottom
R505  0_4  [RC0402]  202.06 43.31 0 bottom
R506  10k_4  [RC0402]  49.3 42.11 90 bottom
R507  *10k_4  [RC0402]  50.44 42.11 90 bottom
R508  *10k_4  [RC0402]  51.59 42.11 90 bottom
R509  4.7k_4  [RC0402]  53.49 42.11 270 bottom
R510  4.7k_4  [RC0402]  54.64 42.11 270 bottom
R511  4.7k_4  [RC0402]  55.78 42.11 270 bottom
R512  4.7k_4  [RC0402]  56.92 42.11 270 bottom
R513  43_4  [RC0402]  58.06 42.11 270 bottom
R514  100k_4  [RC0402]  59.21 42.11 270 bottom
R515  *short_4  [SHORT0402]  62.03 41.66 0 bottom
R516  0_4  [RC0402]  201.3 41.4 0 bottom
R517  100k_4  [RC0402]  64.9 41.53 270 bottom
R519  0_4  [RC0402]  201.3 40.39 0 bottom
R520  24.9/f_4  [RC0402]  164.59 40.31 90 bottom
R521  5.11/f_4  [RC0402]  166.87 40.31 270 bottom
R523  8.2k/f_4  [RC0402]  165.86 38.15 270 bottom
R524  8.2k/f_4  [RC0402]  166.87 38.15 90 bottom
R525  *2.2k_4  [RC0402]  44.2 38.1 0 bottom
R526  15_4  [RC0402]  17.53 37.59 180 bottom
R527  *2.2k_4  [RC0402]  44.2 36.83 0 bottom
R528  15_4  [RC0402]  17.53 36.58 180 bottom
R529  10k_4  [RC0402]  44.2 33.15 0 bottom
R530  *22_4  [RC0402]  66.04 31.5 0 bottom
R531  100k_4  [RC0402]  44.2 31.37 0 bottom
R532  *short_4  [SHORT0402]  66.07 30.35 180 bottom
R535  100k_4  [RC0402]  68.07 27.69 270 bottom
R536  *0_4  [RC0402]  201.17 27.18 0 bottom
R537  2.2k_4  [RC0402]  34.54 26.8 90 bottom
R538  2.2k_4  [RC0402]  35.56 26.8 90 bottom
R539  *short_4  [SHORT0402]  66.09 26.61 0 bottom
R540  *short_4  [SHORT0402]  179.2 26.29 0 bottom
R541  *0_4  [RC0402]  201.17 26.16 0 bottom
R542  *short_4  [SHORT0402]  66.09 25.47 0 bottom
R543  100k_4  [RC0402]  44.7 25.4 90 bottom
R544  *short_4  [SHORT0402]  179.2 25.27 0 bottom
R545  *short_4  [SHORT0402]  179.2 24.26 0 bottom
R546  100k_4  [RC0402]  28.07 23.37 180 bottom
R547  *short_4  [SHORT0402]  179.2 23.24 0 bottom
R548  *0_4  [RC0402]  200.79 23.11 0 bottom
R549  33_4  [RC0402]  41.02 22.48 0 bottom
R551  *0_4  [RC0402]  200.79 22.1 0 bottom
R552  10k_4  [RC0402]  177.87 22.04 180 bottom
R553  *100k_4  [RC0402]  28.07 21.34 180 bottom
R554  *0_4  [RC0402]  177.87 21.02 0 bottom
R555  *0_4  [RC0402]  177.87 20.01 0 bottom
R556  *0_4  [RC0402]  201.68 19.68 0 bottom
R557  *short_6  [SHORT0603]  40.33 19.5 180 bottom
R559  10k_4  [RC0402]  177.87 18.99 180 bottom
R560  *0_4  [RC0402]  201.68 18.67 0 bottom
R561  *0_4  [RC0402]  86.23 18.41 90 bottom
R562  *0_4  [RC0402]  87.25 18.41 270 bottom
R563  *0_4  [RC0402]  88.27 18.41 270 bottom
R564  *0_4  [RC0402]  89.28 18.41 270 bottom
R565  *0_4  [RC0402]  90.3 18.41 270 bottom
R566  *0_4  [RC0402]  91.31 18.41 90 bottom
R567  *0_4  [RC0402]  201.31 16.38 180 bottom
R568  10k_4  [RC0402]  39.5 15.49 90 bottom
R569  10k_4  [RC0402]  40.64 15.49 90 bottom
R570  *0_4  [RC0402]  201.31 15.11 180 bottom
R571  *0_4  [RC0402]  35.56 14.86 180 bottom
R572  *short_4  [SHORT0402]  39.5 13.08 270 bottom
R573  *short_4  [SHORT0402]  40.64 13.08 270 bottom
R574  *short_6  [SHORT0603]  45.59 13.34 180 bottom
R575  2.2k_4  [RC0402]  33.02 12.95 90 bottom
R576  2.2k_4  [RC0402]  38.1 12.95 270 bottom
R577  120_0.3a_4  [RC0402]  42.57 11.79 180 bottom
R578  120_0.3a_4  [RC0402]  42.57 12.8 180 bottom
R579  *short_8  [SHORT0805]  195.39 11.24 0 bottom
R580  10k_4  [RC0402]  33.15 11.05 0 bottom
R581  *0_4  [RC0402]  35.56 11.05 0 bottom
R775  100k_4  [RC0402]  38.67 4 270 top
R776  10k_4  [RC0402]  85.79 66.23 0 bottom
R777  10k_4  [RC0402]  95.32 61.28 0 bottom
R778  10k_4  [RC0402]  88.71 71.57 180 top
R779  *220k/f_4  [RC0402]  152.72 69.03 270 top
R780  *short_4  [SHORT0402]  195.58 80.71 90 bottom
R781  *short_4  [SHORT0402]  37.53 4 90 top
R782  *2m/f_4  [RC0402]  151.58 69.03 90 top
R783  *10k_4  [RC0402]  45.41 5.4 0 top
R784  *22_8  [RC0805]  55.95 4 90 top
R785  *1m_6  [RC0603]  50.1 6.09 90 top
R786  *1m_6  [RC0603]  50.1 3.5 90 top
R787  2.2k_4  [RC0402]  202.5 76.16 0 top
R788  2.2k_4  [RC0402]  202.5 75.02 0 top
RP1  10k_10p8r  [10P8R]  66.04 12.32 90 top
SW1  reset switch  [SW-TC901-AA1G-A160T-6P]  12.81 95.15 0 bottom
SW2  *power switch  [SW-NTC017-BB1J-X160T-4P-SMT]  34.67 52.58 270 bottom
TP1  *pad  [TP2675]  137.54 94.61 0 top
TP2  *pad  [TP2675]  138.48 92.94 0 top
TP3  *pad  [TP2675]  97.94 90.91 0 top
TP4  *pad  [TP2675]  99.85 90.91 0 top
TP5  *pad  [TP2675]  139.04 90.68 180 top
TP6  *pad  [TP2675]  142.62 89.03 180 top
TP7  *pad  [TP2675]  141.48 87.5 180 top
TP8  *pad  [TP2675]  142.62 85.72 180 top
TP9  *pad  [TP2675]  141.35 83.82 180 top
TP10  *pad  [TP2675]  143.26 83.82 180 top
TP11  *pad  [TP2675]  145.16 83.82 180 top
TP12  *pad  [TP2675]  147.07 83.82 180 top
TP13  *pad  [TP2675]  88.67 61.9 0 top
TP14  *pad  [TP2675]  88.54 63.8 0 top
TP15  *pad  [TP2675]  136.52 59.94 0 top
TP16  *pad  [TP2675]  138.43 59.94 0 top
TP17  *pad  [TP2675]  28.32 28.42 270 top
TP18  *pad  [TP2675]  28.7 26.54 270 top
TP19  *pad  [TP2675]  38.35 18.16 90 top
TP20  *pad  [TP2675]  91.82 72.77 0 bottom
TP21  *pad  [TP2675]  88.49 71.45 0 bottom
TP22  *pad  [TP2675]  86.36 67.18 0 bottom
TP23  *pad  [TP2675]  107.06 57.91 0 bottom
TP24  *pad  [TP2675]  205.55 7.43 180 bottom
TP25  *pad  [TP2675]  64.63 29.99 180 bottom
TP26  *pad  [TP2675]  67.71 29.43 180 bottom
U1  *74aup1g07gw  [SOT353-1-2_125-65-5P]  147.32 98.42 180 top
U2  74aup1g07gw  [SOT353-1-2_125-65-5P]  130.43 97.79 270 top
U3  74aup1g07gw  [SOT353-1-2_125-65-5P]  125.65 97.42 270 top
U4  *74cbtlv3126  [VQFN14-3_5X3_5-5-15P]  152.15 93.73 0 top
U5  g5243at11u  [SOT23-2_8-95-6P]  19.81 83.31 270 top
U6  hsw_ult_lpdr3  [BGA1168-INTEL-HASWELL]  117.5 75.5 180 top
U7  74aup1g07gw  [SOT353-1-2_125-65-5P]  146.29 71.16 180 top
U8  apl3510bxi  [MSOP8-4_9-65]  20.35 66.73 0 top
U9  *m24c02-wmn6tp  [SOIC8-6-1_27]  76.34 64.87 0 top
U10  apl3510bxi  [MSOP8-4_9-65]  19.43 38.35 0 top
U11  lpddr3_fpga  [BGA178-HYNIX-H9CCNNNBLTMLAR-NTM]  98.46 38.25 90 top
U12  lpddr3_fpga  [BGA178-HYNIX-H9CCNNNBLTMLAR-NTM]  117.27 38.25 90 top
U13  lpddr3_fpga  [BGA178-HYNIX-H9CCNNNBLTMLAR-NTM]  136.08 38.25 90 top
U14  lpddr3_fpga  [BGA178-HYNIX-H9CCNNNBLTMLAR-NTM]  154.89 38.25 90 top
U15  tpm@npct650  [TSSOP28-6_4-65-SLB9635TT]  74.3 27.3 0 top
U16  alc283  [QFN48-6X6-4-49P-ALC280]  33.91 21.46 90 top
U17  slg55584a  [TDFN8-2X2-5-9P-MAX14566]  20.42 61.59 90 bottom
U18  tc7sh08fu  [SSOP5-P-A-TOSHIBA-B]  90.93 54.79 180 bottom
U19  w25q64fv  -- 8mb  [SOIC8-7_9-1_27-2_16H]  73.15 52.7 180 bottom
U20  tc7sh08fu  [SSOP5-P-A-TOSHIBA-B]  90.93 51.64 180 bottom
U21  tc7sh08fu  [SSOP5-P-A-TOSHIBA-B]  20.57 50.93 180 bottom
U22  apl3510bxi  [MSOP8-4_9-65]  178.94 37.85 0 bottom
U23  it8380e-192/cx  [LQFP128-16X16-4-1_6H]  54.99 31.37 270 bottom
Y1  24mhz  [XTL-3_2X2_5-2_2X1_7-0_8H]  115.56 94.3 0 top
Y2  32.768khz  [XTL-3_2X1_5-2_5-0_8H]  90.3 58.04 0 top

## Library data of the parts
BT1 = BAT-AP-AAA-BAT-054-K01-2P-SMT
C1 C2 C7 C11 C12 C16-C51 C53-C58 C61-C77 C79 C80 C82 C83 C86-C109 C111-C117 C120 C124-C128 C130-C135 C137 C138 C140 C141 C143-C146 C148-C150 C153-C164 C173-C180 C187 C192-C194 C196 C205 C206 C210-C212 C218-C222 C227-C230 C232-C235 C237-C241 C243-C245 C247-C251 C253-C269 C275 C277-C300 C302-C305 C308-C317 C319-C322 C324-C334 C336-C345 C348-C354 C357-C362 C364-C367 C369-C372 C375-C377 C379 C381 C382 C384 C387 C390-C397 C399-C404 C406-C408 C713 C714 D1 D10-D13 D16 PC2 PC6 PC7 PC9 PC11 PC12 PC15 PC28 PC34 PC40 PC43-PC48 PC50 PC54 PC63 PC64 PC68 PC69 PC71-PC77 PC79 PC80 PC84 PC85 PC99 PC122 PC126 PC128 PC133-PC136 = CC0402
C3-C6 C8-C10 C13-C15 C52 C59 C167-C172 C181-C186 C188-C191 C195 C197-C204 C208 C209 C213-C217 C242 PC1 PC3 PC16-PC21 PC26 PC27 PC29-PC31 PC33 PC35-PC37 PC51-PC53 PC61 PC87-PC90 PC98 PC101 PC103 PC105 PC106 PC124 PC125 PC131 = CC0805
C60 C85 C347 C409 = CC3528
C78 C81 C84 C110 C118 C119 C121-C123 C129 C136 C139 C142 C147 C151 C152 C165 C166 C207 C223-C226 C231 C236 C246 C252 C270-C274 C276 C301 C306 C307 C318 C323 C335 C346 C355 C356 C363 C368 C373 C374 C378 C380 C383 C385 C386 C388 C389 C398 C405 C410 C712 PC4 PC5 PC8 PC10 PC22 PC24 PC25 PC32 PC38 PC39 PC41 PC42 PC49 PC55-PC60 PC62 PC65-PC67 PC70 PC78 PC81-PC83 PC86 PC91-PC97 PC100 PC102 PC104 PC108-PC121 PC123 PC127 PC129 PC130 PC132 = CC0603
CLIP1-CLIP11 = EMIPAD47X31-63X24-3P
CLIP12 CLIP13 = EMIPAD63X56
CN1 = BSH-030-01-L-D-A-TR-60P-LDH
CN2 = HDMI-C128F4-K1909-L-19P-SMT
CN3 CN17 CN19 PJ1 = 1775295-4-4P-L
CN4 CN5 = USB-53063-00902-001-9P-SMT
CN6 = PHJK-2SJ3095-033111F-6P
CN7 = LVDS-50473-0200M-001-20P-L
CN8 = LVDS-50473-0300M-V01-30P-L
CN9 = MINIPCI-SM3ZS067U215AE-75P-KE
CN10 CN13 = NGFF-80159-2181-75P-KM
CN11 = 88511-180N-18P-L
CN12 CN16 = 50501-02401-001-24P-L
CN14 = 88511-10XX-10P-L
CN15 = 88513-0801-8P-L
CN18 = 50501-0080N-001-8P-L
CP1-CP6 = 8P4R
D2-D4 D8 D9 D14 D15 D24-D28 PD1 PD2 PD8 = DSM
D5 D6 D17-D23 D29-D31 D33-D35 L14 L18 L19 PR2-PR4 PR6-PR8 PR11-PR13 PR15 PR17 PR19 PR24 PR25 PR28 PR31 PR33 PR35 PR36 PR39 PR41 PR42 PR44 PR45 PR49 PR56-PR60 PR62-PR64 PR66 PR68-PR73 PR76-PR82 PR84-PR92 PR95 PR96 PR99 PR104 PR107 PR111-PR125 PR127-PR129 PR132-PR134 PR137 PR139 PR148 PR149 PR152-PR158 PR160 PR161 PR166-PR170 R2-R6 R8 R9 R12-R25 R27-R30 R32-R43 R45-R66 R68-R74 R76 R78-R89 R92-R100 R103-R142 R144-R149 R151-R153 R155-R158 R160 R161 R163-R167 R169 R171-R181 R183-R193 R201 R204 R206 R207 R209-R212 R214-R219 R221-R223 R226 R227 R229 R231-R287 R291-R293 R295-R297 R299-R302 R304 R305 R309-R312 R318 R330 R331 R334-R336 R338 R340-R347 R349-R365 R368-R380 R383-R385 R387-R391 R393-R395 R397-R400 R403 R406 R409 R410 R412 R413 R417 R418 R420-R433 R436-R445 R449-R452 R454 R455 R457 R459 R460 R465-R472 R474-R482 R484-R486 R488 R490 R491 R493-R514 R516 R517 R519-R521 R523-R531 R535-R538 R541 R543 R546 R548 R549 R551-R556 R559-R571 R575-R578 R580 R581 R775-R779 R782 R783 R787 R788 = RC0402
D7 PQ6 PQ7 PQ9-PQ12 PQ14-PQ19 PQ21-PQ24 PQ27 PQ29 PQ31 PQ32 PQ34 Q1-Q3 Q6 Q7 Q9 Q12-Q16 Q18-Q22 Q24 Q53 Q56 = SOT23_213-3_3-2
D32 = DSMV
HE1 = SOT23_123-2_8-1_9
HOLE1 HOLE5 HOLE8 HOLE12-HOLE14 = H-C236D102P2
HOLE2 = H-TC236BC197D102P2
HOLE3 HOLE18 = H-O98X79D98X79N
HOLE4 = H-TC217BC165D165P2
HOLE6 HOLE7 HOLE9 HOLE10 = H-C150D150N
HOLE11 = O-SKI-1
HOLE15 = H-C217D142P2
HOLE16 = H-C87D87N
J2 = SOLDERJUMPER-2
JP2-JP9 = SHORT3720
L1-L5 L17 PL6-PL9 PR46 PR50 PR54 PR93 PR101 PR102 PR130 PR145 R67 R784 = RC0805
L6-L9 PR5 PR9 PR10 PR16 PR18 PR20 PR21 PR29 PR30 PR38 PR47 PR48 PR52 PR53 PR55 PR75 PR105 PR106 PR135 PR136 PR138 PR141 PR144 PR171 PR172 R194-R198 R203 R298 R303 R322 R323 R326-R329 R386 R392 R401 R407 R408 R458 R785 R786 = RC0603
L11 L15 = FILTER-MCM2012B900GBE-4P
PC13 PC14 PC23 PC107 = CC7343
PD3 = POWER-6_5-1_84-3P
PD4 = D-DO-214AC
PD5-PD7 PQ3 PQ13 PQ20 PQ33 Q4 Q54 Q55 = UMT_213-3-1_3
PJ2 = 50458-00801-V02-8P-L
PL1 = CHOKE-PCMC063T-R82MN-4P-SMT
PL2-PL5 PL10 = CHOKE-PCMC063T-3R3MN-SMT
PQ1 PQ2 PQ4 PQ5 PQ25 PQ26 PQ28 PQ30 PQ38 PQ39 = WDFN5-3_05X3_05-65
PQ8 = IMD
PQ35 PQ36 = SO-8FL-5P-OA
PQ37 Q5 Q8 Q10 Q11 Q17 Q23 Q25 = SC70-2_1-65-6P
PR1 PR131 PR175 R1 R10 R11 R102 R143 R150 R159 R290 R308 R434 R461 R462 R483 R579 = SHORT0805
PR14 PR22 PR23 PR26 PR27 PR32 PR34 PR37 PR40 PR61 PR65 PR83 PR94 PR97 PR98 PR100 PR103 PR108-PR110 PR126 PR146 PR147 PR151 PR162 PR164 PR165 PR173 PR174 PR176 R7 R26 R31 R44 R75 R77 R91 R154 R168 R182 R199 R200 R202 R205 R208 R213 R220 R224 R225 R228 R230 R288 R289 R315 R316 R319-R321 R325 R337 R348 R367 R411 R414-R416 R419 R446-R448 R456 R463 R464 R473 R487 R489 R492 R515 R532 R539 R540 R542 R544 R545 R547 R572 R573 R780 R781 = SHORT0402
PR43 PR51 PR74 PR140 PR142 PR143 PR163 R90 R101 R294 R313 R314 R317 R332 R333 R339 R366 R381 R382 R396 R402 R404 R405 R435 R453 R557 R574 = SHORT0603
PR67 = RC1206
PR150 PR159 = RC3216
PU1 = SON8-4_5X3_5-5-9P-SMT
PU2 PU3 = QFN14-3X3-4-16P
PU4 = QFN20-3X3-4-26P
PU5 = SON10-3X3-5-16P
PU6 = SOT23-6-2_8-95-6P
PU7 = QFN32-4X4-4-42P-1H
PU8 PU10 = SOP8-6-1_27-9P
PU9 U9 = SOIC8-6-1_27
PU11 = PVQFN20-3_5X3_5-5-25P
RP1 = 10P8R
SW1 = SW-TC901-AA1G-A160T-6P
SW2 = SW-NTC017-BB1J-X160T-4P-SMT
TP1-TP26 = TP2675
U1-U3 U7 = SOT353-1-2_125-65-5P
U4 = VQFN14-3_5X3_5-5-15P
U5 = SOT23-2_8-95-6P
U6 = BGA1168-INTEL-HASWELL
U8 U10 U22 = MSOP8-4_9-65
U11-U14 = BGA178-HYNIX-H9CCNNNBLTMLAR-NTM
U15 = TSSOP28-6_4-65-SLB9635TT
U16 = QFN48-6X6-4-49P-ALC280
U17 = TDFN8-2X2-5-9P-MAX14566
U18 U20 U21 = SSOP5-P-A-TOSHIBA-B
U19 = SOIC8-7_9-1_27-2_16H
U23 = LQFP128-16X16-4-1_6H
Y1 = XTL-3_2X2_5-2_2X1_7-0_8H
Y2 = XTL-3_2X1_5-2_5-0_8H

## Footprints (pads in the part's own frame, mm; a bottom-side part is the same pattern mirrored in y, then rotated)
8P4R
  rect 0.406x1.092 smd: 1(-1.194,-0.8) 2(-1.194,0.8) 3(-0.406,-0.8) 4(-0.406,0.8) 5(0.406,-0.8) 6(0.406,0.8) 7(1.194,-0.8) 8(1.194,0.8)
10P8R
  rect 0.305x1.092 smd: 1(-1.27,-0.85) 2(-0.635,-0.85) 3(0,-0.85) 4(0.635,-0.85) 5(1.27,-0.85) 6(1.27,0.85) 7(0.635,0.85) 8(0,0.85) 9(-0.635,0.85) 10(-1.27,0.85)
50458-00801-V02-8P-L
  rect 0.559x1.295 smd: 1(-7,5.025) 2(-5,5.025) 3(-3,5.025) 4(-1,5.025) 5(1,5.025) 6(3,5.025) 7(5,5.025) 8(7,5.025)
  rect 1.295x2.057 smd: 9(-10.1,0) 10(10.1,0)
50501-0080N-001-8P-L
  rect 0.305x1.295 smd: 1(-1.75,2.8) 2(-1.25,2.8) 3(-0.75,2.8) 4(-0.25,2.8) 5(0.25,2.8) 6(0.75,2.8) 7(1.25,2.8) 8(1.75,2.8)
  rect 1.803x1.397 smd: 9(-3.4,0) 10(3.4,0)
50501-02401-001-24P-L
  rect 0.305x1.295 smd: 1(-5.75,2.8) 2(-5.25,2.8) 3(-4.75,2.8) 4(-4.25,2.8) 5(-3.75,2.8) 6(-3.25,2.8) 7(-2.75,2.8) 8(-2.25,2.8) 9(-1.75,2.8) 10(-1.25,2.8) 11(-0.75,2.8) 12(-0.25,2.8) 13(0.25,2.8) 14(0.75,2.8) 15(1.25,2.8) 16(1.75,2.8) 17(2.25,2.8) 18(2.75,2.8) 19(3.25,2.8) 20(3.75,2.8) 21(4.25,2.8) 22(4.75,2.8) 23(5.25,2.8) 24(5.75,2.8)
  rect 1.803x1.397 smd: 25(-7.4,0) 26(7.4,0)
88511-10XX-10P-L
  rect 0.305x1.295 smd: 1(-2.25,2.8) 2(-1.75,2.8) 3(-1.25,2.8) 4(-0.75,2.8) 5(-0.25,2.8) 6(0.25,2.8) 7(0.75,2.8) 8(1.25,2.8) 9(1.75,2.8) 10(2.25,2.8)
  rect 1.803x1.397 smd: 11(-3.9,0) 12(3.9,0)
88511-180N-18P-L
  rect 0.305x1.295 smd: 1(-4.25,2.8) 2(-3.75,2.8) 3(-3.25,2.8) 4(-2.75,2.8) 5(-2.25,2.8) 6(-1.75,2.8) 7(-1.25,2.8) 8(-0.75,2.8) 9(-0.25,2.8) 10(0.25,2.8) 11(0.75,2.8) 12(1.25,2.8) 13(1.75,2.8) 14(2.25,2.8) 15(2.75,2.8) 16(3.25,2.8) 17(3.75,2.8) 18(4.25,2.8)
  rect 1.803x1.397 smd: 19(-5.9,0) 20(5.9,0)
88513-0801-8P-L
  rect 0.508x1.295 smd: 1(-3.5,0) 2(-2.5,0) 3(-1.5,0) 4(-0.5,0) 5(0.5,0) 6(1.5,0) 7(2.5,0) 8(3.5,0)
  rect 1.803x1.397 smd: 9(-5.65,-2.8) 10(5.65,-2.8)
1775295-4-4P-L
  rect 0.787x1.905 smd: 1(-1.875,3.5) 2(-0.625,3.5) 3(0.625,3.5) 4(1.875,3.5)
  rect 1.295x3.353 smd: 5(-4.725,-1.375) 6(4.725,-1.375)
BAT-AP-AAA-BAT-054-K01-2P-SMT
  round 1.397 hole 1.397 unplated: (0,8)
  round 0.991 hole 0.991 unplated: (0,-8)
  rect 3.505x3.988 smd: 1(15.25,0) 2(-16.35,0)
BGA178-HYNIX-H9CCNNNBLTMLAR-NTM
  round 0.356 smd: A1(-4.8,5.2) A2(-4,5.2) A3(-3.2,5.2) A4(-2.4,5.2) A5(-1.6,5.2) A6(-0.8,5.2) A8(0.8,5.2) A9(1.6,5.2) A10(2.4,5.2) A11(3.2,5.2) A12(4,5.2) A13(4.8,5.2) B1(-4.8,4.55) B2(-4,4.55) B3(-3.2,4.55) B4(-2.4,4.55) B5(-1.6,4.55) B6(-0.8,4.55) B8(0.8,4.55) B9(1.6,4.55) B10(2.4,4.55) B11(3.2,4.55) B12(4,4.55) B13(4.8,4.55) C2(-4,3.9) C3(-3.2,3.9) C4(-2.4,3.9) C5(-1.6,3.9) C6(-0.8,3.9) C8(0.8,3.9) C9(1.6,3.9) C10(2.4,3.9) C11(3.2,3.9) C12(4,3.9) D2(-4,3.25) D3(-3.2,3.25) D4(-2.4,3.25) D5(-1.6,3.25) D6(-0.8,3.25) D8(0.8,3.25) D9(1.6,3.25) D10(2.4,3.25) D11(3.2,3.25) D12(4,3.25) E2(-4,2.6) E3(-3.2,2.6) E4(-2.4,2.6) E5(-1.6,2.6) E6(-0.8,2.6) E8(0.8,2.6) E9(1.6,2.6) E10(2.4,2.6) E11(3.2,2.6) E12(4,2.6) F2(-4,1.95) F3(-3.2,1.95) F4(-2.4,1.95) F5(-1.6,1.95) F6(-0.8,1.95) F8(0.8,1.95) F9(1.6,1.95) F10(2.4,1.95) F11(3.2,1.95) F12(4,1.95) G2(-4,1.3) G3(-3.2,1.3) G4(-2.4,1.3) G5(-1.6,1.3) G6(-0.8,1.3) G8(0.8,1.3) G9(1.6,1.3) G10(2.4,1.3) G11(3.2,1.3) G12(4,1.3) H2(-4,0.65) H3(-3.2,0.65) H4(-2.4,0.65) H5(-1.6,0.65) H6(-0.8,0.65) H8(0.8,0.65) H9(1.6,0.65) H10(2.4,0.65) H11(3.2,0.65) H12(4,0.65) J2(-4,0) J3(-3.2,0) J4(-2.4,0) J5(-1.6,0) J6(-0.8,0) J8(0.8,0) J9(1.6,0) J10(2.4,0) J11(3.2,0) J12(4,0) K2(-4,-0.65) K3(-3.2,-0.65) K4(-2.4,-0.65) K5(-1.6,-0.65) K6(-0.8,-0.65) K8(0.8,-0.65) K9(1.6,-0.65) K10(2.4,-0.65) K11(3.2,-0.65) K12(4,-0.65) L2(-4,-1.3) L3(-3.2,-1.3) L4(-2.4,-1.3) L5(-1.6,-1.3) L6(-0.8,-1.3) L8(0.8,-1.3) L9(1.6,-1.3) L10(2.4,-1.3) L11(3.2,-1.3) L12(4,-1.3) M2(-4,-1.95) M3(-3.2,-1.95) M4(-2.4,-1.95) M5(-1.6,-1.95) M6(-0.8,-1.95) M8(0.8,-1.95) M9(1.6,-1.95) M10(2.4,-1.95) M11(3.2,-1.95) M12(4,-1.95) N2(-4,-2.6) N3(-3.2,-2.6) N4(-2.4,-2.6) N5(-1.6,-2.6) N6(-0.8,-2.6) N8(0.8,-2.6) N9(1.6,-2.6) N10(2.4,-2.6) N11(3.2,-2.6) N12(4,-2.6) P2(-4,-3.25) P3(-3.2,-3.25) P4(-2.4,-3.25) P5(-1.6,-3.25) P6(-0.8,-3.25) P8(0.8,-3.25) P9(1.6,-3.25) P10(2.4,-3.25) P11(3.2,-3.25) P12(4,-3.25) R2(-4,-3.9) R3(-3.2,-3.9) R4(-2.4,-3.9) R5(-1.6,-3.9) R6(-0.8,-3.9) R8(0.8,-3.9) R9(1.6,-3.9) R10(2.4,-3.9) R11(3.2,-3.9) R12(4,-3.9) T1(-4.8,-4.55) T2(-4,-4.55) T3(-3.2,-4.55) T4(-2.4,-4.55) T5(-1.6,-4.55) T6(-0.8,-4.55) T8(0.8,-4.55) T9(1.6,-4.55) T10(2.4,-4.55) T11(3.2,-4.55) T12(4,-4.55) T13(4.8,-4.55) U1(-4.8,-5.2) U2(-4,-5.2) U3(-3.2,-5.2) U4(-2.4,-5.2) U5(-1.6,-5.2) U6(-0.8,-5.2) U8(0.8,-5.2) U9(1.6,-5.2) U10(2.4,-5.2) U11(3.2,-5.2) U12(4,-5.2) U13(4.8,-5.2)
BGA1168-INTEL-HASWELL
  round 0.508 smd: A3(18.177,-11.314) A62(-18.722,-11.314) AW1(19.314,10.727) AW63(-19.314,10.743) AY2(18.771,11.314) AY62(-18.748,11.314) B2(18.806,-10.806) B63(-19.314,-10.722) C1(19.314,-10.177)
  round 0.381 smd: A4(17.421,-11.314) A5(16.76,-11.314) A6(15.564,-11.314) A59(-16.586,-11.314) A60(-17.412,-11.314) A61(-18.072,-11.314) AA9(14.282,0.262) AA21(7.627,0.175) AA23(6.199,0.175) AA58(-16.063,0.015) AB10(13.838,0.738) AB20(8.135,0.582) AB21(7.627,0.988) AB22(6.707,0.582) AB23(6.199,0.988) AB57(-15.743,0.666) AC9(14.282,1.215) AC20(8.135,1.394) AC22(6.707,1.394) AC58(-16.063,1.316) AD10(13.838,1.691) AD21(7.627,1.801) AD23(6.199,1.801) AD57(-15.743,1.966) AE9(14.282,2.167) AE10(13.838,2.643) AE20(8.135,2.207) AE21(7.627,2.614) AE22(6.707,2.207) AE23(6.199,2.614) AE58(-16.063,2.616) AF9(14.282,3.12) AF11(13.255,2.968) AF12(12.442,2.968) AF14(11.63,2.968) AF15(10.817,2.968) AF17(10.004,2.968) AF18(9.191,2.968) AF20(8.378,2.968) AF22(6.707,3.02) AG10(13.662,3.476) AG11(12.849,3.476) AG13(12.036,3.476) AG14(11.223,3.476) AG16(10.41,3.476) AG17(9.598,3.476) AG19(8.785,3.476) AG20(7.972,3.476) AG23(6.199,3.426) AG57(-15.743,3.267) AG58(-16.377,3.695) AH22(6.707,3.833) AH24(5.394,3.975) AH26(4.094,3.975) AH28(2.793,3.975) AH30(1.493,3.975) AH32(0.192,3.975) AH34(-1.108,3.975) AH36(-2.409,3.975) AH38(-3.709,3.975) AH40(-5.01,3.975) AH42(-6.31,3.975) AH44(-7.611,3.975) AH46(-8.911,3.975) AH49(-10.212,3.975) AH51(-11.512,3.975) AH53(-12.813,3.975) AH55(-14.113,3.975) AH57(-15.413,3.975) AJ23(6.199,4.239) AJ25(4.744,4.3) AJ27(3.443,4.3) AJ29(2.143,4.3) AJ31(0.843,4.3) AJ33(-0.458,4.3) AJ35(-1.758,4.3) AJ37(-3.059,4.3) AJ39(-4.359,4.3) AJ41(-5.66,4.3) AJ43(-6.96,4.3) AJ45(-8.261,4.3) AJ47(-9.561,4.3) AJ50(-10.862,4.3) AJ52(-12.162,4.3) AJ54(-13.463,4.3) AJ56(-14.763,4.3) AJ58(-16.064,4.3) AT1(19.314,8.683) AT63(-19.314,8.533) AU1(19.314,9.343) AU63(-19.314,9.359) AV1(19.314,10.004) AV2(18.654,9.993) AV62(-18.664,10.004) AV63(-19.314,10.019) AW2(18.654,10.654) AW3(17.993,10.654) AW61(-18.014,10.664) AW62(-18.664,10.664) AY3(18.047,11.314) AY4(17.387,11.314) AY5(16.726,11.314) AY59(-16.774,11.314) AY60(-17.434,11.314) AY61(-18.095,11.314) B3(18.056,-10.664) B61(-18.001,-10.654) B62(-18.664,-10.59) C2(18.664,-10.056) C62(-18.664,-9.93) C63(-19.314,-9.998) D1(19.314,-9.453) D63(-19.314,-9.338) E1(19.314,-8.792) E23(5.981,-8.713) E25(4.6,-8.713) E27(3.474,-8.713) E29(2.093,-8.713) E31(0.966,-8.713) E33(-0.415,-8.713) E35(-1.541,-8.713) E37(-2.922,-8.713) E39(-4.049,-8.713) E41(-5.43,-8.713) E43(-6.556,-8.713) E45(-7.937,-8.713) E47(-9.064,-8.713) E49(-10.444,-8.713) E51(-11.571,-8.713) E53(-12.952,-8.713) E55(-14.079,-8.713) E57(-15.459,-8.713) E63(-19.314,-8.667) F1(19.314,-7.878) F22(6.597,-8.256) F24(5.291,-8.188) F26(4.037,-8.188) F28(2.783,-8.188) F30(1.53,-8.188) F32(0.276,-8.188) F34(-0.978,-8.188) F36(-2.232,-8.188) F38(-3.485,-8.188) F40(-4.739,-8.188) F42(-5.993,-8.188) F44(-7.247,-8.188) F46(-8.5,-8.188) F48(-9.754,-8.188) F50(-11.008,-8.188) F52(-12.262,-8.188) F54(-13.515,-8.188) F56(-14.769,-8.188) F58(-16.063,-8.188) G22(6.707,-7.546) G23(5.981,-7.863) G25(4.6,-7.863) G27(3.474,-7.863) G29(2.093,-7.863) G31(0.966,-7.863) G33(-0.415,-7.863) G35(-1.541,-7.863) G37(-2.922,-7.863) G39(-4.049,-7.863) G41(-5.43,-7.863) G43(-6.556,-7.863) G45(-7.937,-7.863) G47(-9.064,-7.863) G49(-10.444,-7.863) G51(-11.571,-7.863) G53(-12.952,-7.863) G55(-14.079,-7.863) G57(-15.459,-7.863) H22(6.707,-6.734) H23(6.199,-7.14) H57(-15.743,-7.213) J22(6.707,-5.921) J23(6.199,-6.327) J58(-16.063,-6.487) K9(14.282,-5.453) K10(13.379,-5.614) K12(12.426,-5.614) K14(11.474,-5.614) K16(10.521,-5.614) K18(9.569,-5.614) K19(8.616,-5.614) K21(7.664,-5.614) K23(6.199,-5.514) K57(-15.743,-5.837) L10(13.838,-4.977) L11(12.902,-5.17) L13(11.95,-5.17) L15(10.997,-5.17) L17(10.045,-5.17) L18(9.092,-5.17) L20(8.135,-5.108) L22(6.707,-5.108) L58(-16.063,-5.186) M9(14.282,-4.5) M20(8.135,-4.295) M21(7.627,-4.702) M22(6.707,-4.295) M23(6.199,-4.702) M57(-15.743,-4.536) N10(13.838,-4.024) N21(7.627,-3.889) N23(6.199,-3.889) N58(-16.063,-3.886) P9(14.282,-3.548) P20(8.135,-3.482) P22(6.707,-3.482) P57(-15.743,-3.236) R10(13.838,-3.072) R20(8.135,-2.67) R21(7.627,-3.076) R22(6.707,-2.67) R23(6.199,-3.076) T9(14.282,-2.595) T21(7.627,-2.263) T23(6.199,-2.263) T58(-16.063,-2.585) U9(14.282,-1.643) U10(13.838,-2.119) U20(8.135,-1.857) U22(6.707,-1.857) U57(-15.743,-1.935) V10(13.838,-1.167) V21(7.627,-1.45) V23(6.199,-1.45) V58(-16.063,-1.285) W9(14.282,-0.69) W20(8.135,-1.044) W21(7.627,-0.638) W22(6.707,-1.044) W23(6.199,-0.638) W57(-15.743,-0.635) Y10(13.838,-0.214) Y20(8.135,-0.231) Y22(6.707,-0.231)
  round 0.305 smd: A8(14.776,-11.314) A9(13.862,-11.314) A11(12.948,-11.314) A12(12.198,-11.314) A14(11.284,-11.314) A15(10.37,-11.314) A17(9.62,-11.314) A18(8.706,-11.314) A20(7.791,-11.314) A21(7.042,-11.314) A23(6.128,-11.314) A24(5.291,-10.989) A25(4.6,-11.314) A27(3.474,-11.314) A28(2.783,-10.989) A29(2.093,-11.314) A31(0.966,-11.314) A32(0.276,-10.989) A33(-0.415,-11.314) A35(-1.541,-11.314) A36(-2.232,-10.989) A37(-2.922,-11.314) A39(-4.049,-11.314) A40(-4.739,-10.989) A41(-5.43,-11.314) A43(-6.556,-11.314) A44(-7.247,-10.989) A45(-7.937,-11.314) A47(-9.064,-11.314) A48(-9.754,-10.989) A49(-10.444,-11.314) A51(-11.571,-11.314) A52(-12.262,-10.989) A53(-12.952,-11.314) A55(-14.079,-11.314) A56(-14.769,-10.989) A57(-15.459,-11.314) AA1(19.314,0.402) AA2(18.664,0.402) AA3(18.014,0.364) AA4(17.363,0.364) AA59(-16.713,0.324) AA60(-17.363,0.324) AA61(-18.014,0.324) AA62(-18.664,0.362) AA63(-19.314,0.362) AB5(16.678,0.738) AB6(16.027,0.738) AB7(15.377,0.738) AB8(14.727,0.738) AC1(19.314,1.152) AC2(18.664,1.152) AC3(18.014,1.19) AC4(17.363,1.19) AC59(-16.713,1.15) AC60(-17.363,1.15) AC61(-18.014,1.15) AC62(-18.664,1.112) AC63(-19.314,1.112) AD1(19.314,1.901) AD2(18.664,1.901) AD3(18.014,1.863) AD4(17.363,1.863) AD5(16.678,1.691) AD6(16.027,1.691) AD7(15.377,1.691) AD8(14.727,1.691) AD59(-16.713,1.823) AD60(-17.363,1.823) AD61(-18.014,1.823) AD62(-18.664,1.861) AD63(-19.314,1.861) AE5(16.678,2.643) AE6(16.027,2.643) AE7(15.377,2.643) AE8(14.727,2.643) AE59(-16.713,2.648) AE60(-17.363,2.648) AE61(-18.014,2.648) AE62(-18.664,2.61) AE63(-19.314,2.61) AF1(19.314,2.65) AF2(18.664,2.65) AF3(18.014,2.688) AF4(17.363,2.688) AG1(19.314,3.4) AG2(18.664,3.4) AG3(18.014,3.361) AG4(17.363,3.361) AG5(16.678,3.596) AG6(16.027,3.596) AG7(15.377,3.596) AG8(14.727,3.596) AG21(7.359,3.807) AG60(-17.038,3.288) AG61(-17.689,3.288) AG62(-18.339,3.288) AG63(-18.989,3.288) AH1(19.314,4.149) AH2(18.664,4.149) AH3(18.014,4.187) AH4(17.363,4.187) AH10(13.662,4.162) AH11(12.849,4.162) AH13(12.036,4.162) AH14(11.223,4.162) AH16(10.41,4.162) AH17(9.598,4.162) AH19(8.785,4.162) AH20(7.972,4.162) AH60(-17.363,3.964) AH61(-18.014,3.964) AH62(-18.664,3.964) AH63(-19.314,3.964) AJ5(16.678,4.548) AJ6(16.027,4.548) AJ7(15.377,4.548) AJ8(14.727,4.548) AJ10(13.662,4.812) AJ11(12.849,4.812) AJ13(12.036,4.812) AJ14(11.223,4.812) AJ60(-17.038,4.64) AJ61(-17.689,4.64) AJ62(-18.339,4.64) AJ63(-18.989,4.64) AK1(19.314,4.898) AK2(18.664,4.898) AK3(18.014,4.86) AK4(17.363,4.86) AK8(15.011,5.137) AK18(9.466,4.952) AK20(8.513,4.952) AK21(7.561,4.952) AK60(-17.363,5.209) AK61(-18.014,5.209) AK62(-18.664,5.315) AK63(-19.314,5.315) AL1(19.314,5.647) AL2(18.664,5.647) AL3(18.014,5.686) AL4(17.363,5.686) AL5(16.413,5.462) AL7(15.575,5.462) AL8(15.011,5.787) AL10(13.657,5.462) AL11(13.093,5.787) AL13(11.738,5.462) AL15(11.174,5.787) AL17(10.092,5.268) AL18(9.466,5.602) AL20(8.513,5.602) AL21(7.561,5.602) AL22(6.608,5.602) AL23(5.786,5.602) AL25(4.81,5.602) AL26(3.858,5.602) AL28(2.905,5.602) AL29(1.953,5.602) AL31(1.054,5.277) AL32(0.49,5.602) AL33(-0.412,5.602) AL35(-1.415,5.602) AL36(-2.266,5.602) AL38(-3.32,5.602) AL39(-4.228,5.277) AL40(-4.817,5.602) AL42(-5.63,5.602) AL43(-6.582,5.602) AL45(-7.56,5.602) AL46(-8.487,5.602) AL48(-9.542,5.602) AL49(-10.443,5.602) AL51(-11.447,5.602) AL52(-12.269,5.602) AL54(-13.295,5.602) AL55(-14.248,5.602) AL57(-15.195,5.602) AL58(-16.094,5.602) AL60(-17.038,5.855) AL61(-17.689,5.855) AM1(19.314,6.397) AM2(18.664,6.397) AM3(18.014,6.359) AM4(17.363,6.359) AM5(16.413,6.112) AM7(15.575,6.112) AM8(15.011,6.437) AM10(13.657,6.112) AM11(13.093,6.437) AM13(11.738,6.112) AM15(11.174,6.437) AM17(10.092,5.919) AM18(9.466,6.252) AM20(8.513,6.252) AM21(7.561,6.252) AM22(6.608,6.252) AM23(5.786,6.252) AM25(4.81,6.252) AM26(3.858,6.252) AM28(2.905,6.252) AM29(1.953,6.252) AM31(1.054,5.927) AM32(0.49,6.252) AM33(-0.412,6.252) AM35(-1.415,6.252) AM36(-2.266,6.252) AM38(-3.32,6.252) AM40(-4.817,6.252) AM42(-5.63,6.252) AM43(-6.582,6.252) AM45(-7.56,6.252) AM46(-8.487,6.252) AM48(-9.542,6.252) AM49(-10.443,6.252) AM51(-11.447,6.252) AM52(-12.269,6.252) AM54(-13.295,6.252) AM55(-14.248,6.252) AM57(-15.195,6.252) AM58(-16.094,6.252) AM60(-17.363,6.501) AM61(-18.014,6.501) AM62(-18.664,6.395) AM63(-19.314,6.395) AN1(19.314,7.146) AN2(18.664,7.146) AN3(18.014,7.184) AN4(17.363,7.184) AN5(16.413,6.762) AN7(15.575,6.762) AN8(15.011,7.088) AN10(13.657,6.762) AN11(13.093,7.088) AN13(11.738,6.762) AN15(11.174,7.088) AN17(10.092,6.569) AN18(9.466,6.903) AN20(8.513,6.903) AN21(7.561,6.903) AN22(6.608,6.903) AN23(5.786,6.903) AN25(4.81,6.903) AN26(3.858,6.903) AN28(2.905,6.903) AN29(1.953,6.903) AN31(1.054,6.578) AN32(0.49,6.903) AN33(-0.412,6.903) AN35(-1.415,6.903) AN36(-2.266,6.903) AN38(-3.32,6.903) AN39(-4.228,6.578) AN40(-4.817,6.903) AN42(-5.63,6.903) AN43(-6.582,6.903) AN45(-7.56,6.903) AN46(-8.487,6.903) AN48(-9.542,6.903) AN49(-10.443,6.903) AN51(-11.447,6.903) AN52(-12.269,6.903) AN54(-13.295,6.903) AN55(-14.248,6.903) AN57(-15.195,6.903) AN58(-16.094,6.903) AN60(-17.038,7.07) AN61(-17.689,7.07) AN62(-18.339,7.07) AN63(-18.989,7.07) AP1(19.314,7.895) AP2(18.664,7.895) AP3(18.014,7.857) AP4(17.363,7.857) AP5(16.413,7.413) AP7(15.575,7.413) AP8(15.011,7.738) AP10(13.657,7.413) AP11(13.093,7.738) AP13(11.738,7.413) AP15(11.174,7.738) AP17(10.092,7.219) AP18(9.466,7.553) AP20(8.513,7.553) AP21(7.561,7.553) AP22(6.608,7.553) AP23(5.786,7.553) AP25(4.81,7.553) AP26(3.858,7.553) AP28(2.905,7.553) AP29(1.953,7.553) AP31(1.054,7.228) AP32(0.49,7.553) AP33(-0.412,7.553) AP35(-1.415,7.553) AP36(-2.266,7.553) AP38(-3.32,7.553) AP39(-4.228,7.228) AP40(-4.817,7.553) AP42(-5.63,7.553) AP43(-6.582,7.553) AP45(-7.56,7.553) AP46(-8.487,7.553) AP48(-9.542,7.553) AP49(-10.443,7.553) AP51(-11.447,7.553) AP52(-12.269,7.553) AP54(-13.295,7.553) AP55(-14.248,7.553) AP57(-15.195,7.553) AP58(-16.094,7.553) AP60(-17.363,7.746) AP61(-18.014,7.746) AP62(-18.664,7.746) AP63(-19.314,7.746) AR5(16.413,8.063) AR7(15.575,8.063) AR8(15.011,8.388) AR10(13.657,8.063) AR11(13.093,8.388) AR13(11.738,8.063) AR15(11.174,8.388) AR17(10.092,7.869) AR18(9.466,8.203) AR20(8.513,8.203) AR21(7.561,8.203) AR22(6.608,8.203) AR23(5.786,8.203) AR25(4.81,8.203) AR26(3.858,8.203) AR28(2.905,8.203) AR29(1.953,8.203) AR31(1.054,7.878) AR32(0.49,8.203) AR33(-0.412,8.203) AR35(-1.415,8.203) AR36(-2.266,8.203) AR38(-3.32,8.203) AR39(-4.228,7.878) AR40(-4.817,8.203) AR42(-5.63,8.203) AR43(-6.582,8.203) AR45(-7.56,8.203) AR46(-8.487,8.203) AR48(-9.542,8.203) AR49(-10.443,8.203) AR51(-11.447,8.203) AR52(-12.269,8.203) AR54(-13.295,8.203) AR55(-14.248,8.203) AR57(-15.195,8.203) AR58(-16.094,8.203) AT2(18.664,8.645) AT3(18.014,8.683) AT4(17.363,8.683) AT5(16.413,8.713) AT7(15.575,8.713) AT10(13.657,8.713) AT13(11.738,8.713) AT35(-1.122,8.905) AT37(-2.697,8.905) AT40(-4.272,8.905) AT42(-5.847,8.905) AT43(-7.422,8.905) AT46(-8.996,8.905) AT49(-10.597,8.933) AT61(-17.689,8.32) AT62(-18.498,8.376) AU2(18.659,9.333) AU3(17.999,9.333) AU4(17.338,9.333) AU6(15.977,9.363) AU7(15.151,9.363) AU8(14.478,9.363) AU10(13.653,9.363) AU11(12.98,9.363) AU12(12.154,9.363) AU14(11.481,9.363) AU15(10.656,9.363) AU16(10.092,9.038) AU17(9.454,9.363) AU18(8.778,9.038) AU19(8.21,9.363) AU20(7.563,9.038) AU21(6.917,9.363) AU22(6.348,9.038) AU23(5.672,9.363) AU24(4.996,9.038) AU25(4.321,9.363) AU26(3.645,9.038) AU27(3.076,9.363) AU28(2.43,9.038) AU29(1.783,9.363) AU30(1.214,9.038) AU31(0.539,9.363) AU33(-0.058,9.016) AU34(-0.66,9.363) AU35(-1.585,9.363) AU36(-2.235,9.363) AU37(-3.16,9.363) AU39(-3.81,9.363) AU40(-4.734,9.363) AU41(-5.385,9.363) AU42(-6.309,9.363) AU43(-6.959,9.363) AU44(-7.884,9.363) AU46(-8.534,9.363) AU47(-9.459,9.363) AU49(-10.109,9.363) AU50(-11.086,9.363) AU51(-11.666,9.038) AU52(-12.342,9.363) AU53(-13.017,9.038) AU54(-13.586,9.363) AU55(-14.233,9.038) AU56(-14.879,9.363) AU57(-15.448,9.038) AU58(-16.124,9.363) AU59(-16.688,9.038) AU60(-17.251,9.363) AU61(-17.963,9.087) AU62(-18.664,9.349) AV3(17.993,9.993) AV4(17.338,9.993) AV5(16.65,10.014) AV6(15.977,10.014) AV7(15.151,10.014) AV8(14.478,10.014) AV10(13.653,10.014) AV11(12.98,10.014) AV12(12.154,10.014) AV14(11.481,10.014) AV15(10.656,10.014) AV16(10.092,9.689) AV17(9.454,10.014) AV18(8.778,9.689) AV19(8.21,10.014) AV20(7.563,9.689) AV21(6.917,10.014) AV22(6.348,9.689) AV23(5.672,10.014) AV24(4.996,9.689) AV25(4.321,10.014) AV26(3.645,9.689) AV27(3.076,10.014) AV28(2.43,9.689) AV29(1.783,10.014) AV30(1.214,9.689) AV31(0.539,10.014) AV33(-0.086,9.689) AV34(-0.71,10.014) AV35(-1.535,10.014) AV36(-2.284,10.014) AV37(-3.11,10.014) AV39(-3.859,10.014) AV40(-4.685,10.014) AV41(-5.434,10.014) AV42(-6.26,10.014) AV43(-7.009,10.014) AV44(-7.834,10.014) AV46(-8.584,10.014) AV47(-9.409,10.014) AV49(-10.158,10.014) AV50(-10.984,10.014) AV51(-11.666,9.689) AV52(-12.342,10.014) AV53(-13.017,9.689) AV54(-13.586,10.014) AV55(-14.233,9.689) AV56(-14.879,10.014) AV57(-15.448,9.689) AV58(-16.124,10.014) AV59(-16.688,9.689) AV60(-17.251,10.014) AV61(-17.988,9.737) AW4(17.338,10.654) AW5(16.688,10.664) AW6(15.939,10.664) AW7(15.189,10.664) AW8(14.44,10.664) AW10(13.691,10.664) AW11(12.942,10.664) AW12(12.192,10.664) AW14(11.443,10.664) AW15(10.694,10.664) AW16(10.092,10.339) AW17(9.454,10.664) AW18(8.778,10.339) AW19(8.103,10.664) AW21(7.023,10.664) AW22(6.348,10.339) AW23(5.672,10.664) AW24(4.996,10.339) AW25(4.321,10.664) AW26(3.645,10.339) AW27(2.97,10.664) AW29(1.89,10.664) AW30(1.214,10.339) AW31(0.539,10.664) AW33(-0.137,10.339) AW34(-0.71,10.664) AW35(-1.535,10.664) AW36(-2.284,10.664) AW37(-3.11,10.664) AW39(-3.859,10.664) AW40(-4.685,10.664) AW41(-5.434,10.664) AW42(-6.26,10.664) AW43(-7.009,10.664) AW44(-7.834,10.664) AW46(-8.584,10.664) AW47(-9.409,10.664) AW49(-10.158,10.664) AW50(-10.984,10.664) AW51(-11.666,10.339) AW52(-12.342,10.664) AW53(-13.017,10.339) AW54(-13.693,10.664) AW56(-14.772,10.664) AW57(-15.448,10.339) AW58(-16.124,10.664) AW59(-16.688,10.339) AW60(-17.251,10.664) AY6(15.939,11.314) AY7(15.189,11.314) AY8(14.44,11.314) AY10(13.691,11.314) AY11(12.942,11.314) AY12(12.192,11.314) AY14(11.443,11.314) AY15(10.694,11.314) AY16(10.13,10.989) AY17(9.454,11.314) AY18(8.778,10.989) AY19(8.103,11.314) AY21(7.023,11.314) AY22(6.348,10.989) AY23(5.672,11.314) AY24(4.996,10.989) AY25(4.321,11.314) AY26(3.645,10.989) AY27(2.97,11.314) AY29(1.89,11.314) AY30(1.214,10.989) AY31(0.539,11.314) AY33(-0.137,10.989) AY34(-0.71,11.314) AY35(-1.535,11.314) AY36(-2.284,11.314) AY37(-3.11,11.314) AY39(-3.859,11.314) AY40(-4.685,11.314) AY41(-5.434,11.314) AY42(-6.26,11.314) AY43(-7.009,11.314) AY44(-7.834,11.314) AY46(-8.584,11.314) AY47(-9.409,11.314) AY49(-10.158,11.314) AY50(-10.984,11.314) AY51(-11.666,10.989) AY52(-12.342,11.314) AY53(-13.017,10.989) AY54(-13.693,11.314) AY56(-14.772,11.314) AY57(-15.448,10.989) AY58(-16.124,11.314) B4(17.393,-10.664) B5(16.176,-10.672) B6(15.196,-10.672) B8(14.423,-10.672) B9(13.598,-10.672) B11(12.617,-10.672) B12(11.845,-10.672) B14(11.02,-10.672) B15(10.039,-10.672) B17(9.267,-10.672) B18(8.442,-10.672) B20(7.461,-10.672) B21(7.042,-10.118) B22(6.689,-10.672) B23(5.864,-10.672) B24(5.291,-10.339) B25(4.6,-10.664) B26(4.037,-10.339) B27(3.474,-10.664) B28(2.783,-10.339) B29(2.093,-10.664) B30(1.53,-10.339) B31(0.966,-10.664) B32(0.276,-10.339) B33(-0.415,-10.664) B34(-0.978,-10.339) B35(-1.541,-10.664) B36(-2.232,-10.339) B37(-2.922,-10.664) B38(-3.485,-10.339) B39(-4.049,-10.664) B40(-4.739,-10.339) B41(-5.43,-10.664) B42(-5.993,-10.339) B43(-6.556,-10.664) B44(-7.247,-10.339) B45(-7.937,-10.664) B46(-8.5,-10.339) B47(-9.064,-10.664) B48(-9.754,-10.339) B49(-10.444,-10.664) B50(-11.008,-10.339) B51(-11.571,-10.664) B52(-12.262,-10.339) B53(-12.952,-10.664) B54(-13.515,-10.339) B55(-14.079,-10.664) B56(-14.769,-10.339) B57(-15.459,-10.664) B58(-16.023,-10.339) B59(-16.586,-10.664) B60(-17.351,-10.654) C3(18.012,-10.012) C4(17.196,-10.042) C5(16.542,-10.118) C6(15.538,-10.118) C8(14.776,-10.118) C9(13.964,-10.118) C11(12.96,-10.118) C12(12.198,-10.118) C14(11.386,-10.118) C15(10.382,-10.118) C17(9.62,-10.118) C18(8.807,-10.118) C20(7.804,-10.118) C21(7.423,-9.529) C22(6.636,-9.529) C23(6.229,-10.118) C24(5.263,-9.282) C25(4.6,-10.014) C26(4.037,-9.689) C27(3.474,-10.014) C28(2.756,-9.282) C29(2.093,-10.014) C30(1.53,-9.689) C31(0.966,-10.014) C32(0.248,-9.282) C33(-0.415,-10.014) C34(-0.978,-9.689) C35(-1.541,-10.014) C36(-2.259,-9.282) C37(-2.922,-10.014) C38(-3.485,-9.689) C39(-4.049,-10.014) C40(-4.767,-9.282) C41(-5.43,-10.014) C42(-5.993,-9.689) C43(-6.556,-10.014) C44(-7.274,-9.282) C45(-7.937,-10.014) C46(-8.5,-9.689) C47(-9.064,-10.014) C48(-9.756,-9.282) C49(-10.444,-10.014) C50(-11.008,-9.689) C51(-11.571,-10.014) C52(-12.264,-9.323) C53(-12.952,-10.014) C54(-13.515,-9.689) C55(-14.079,-10.014) C56(-14.771,-9.323) C57(-15.459,-10.014) C58(-16.023,-9.689) C59(-16.586,-10.014) C61(-17.689,-10.077) D2(18.664,-9.24) D3(18.014,-9.278) D5(16.636,-9.472) D6(15.945,-9.529) D8(15.157,-9.529) D9(14.37,-9.529) D11(13.462,-9.529) D12(12.579,-9.529) D14(11.792,-9.529) D15(10.884,-9.529) D17(10.001,-9.529) D18(9.214,-9.529) D20(8.306,-9.529) D21(7.079,-8.891) D23(5.937,-9.529) D25(4.6,-9.363) D26(4.037,-9.038) D27(3.474,-9.363) D29(2.093,-9.363) D30(1.53,-9.038) D31(0.966,-9.363) D33(-0.415,-9.363) D34(-0.978,-9.038) D35(-1.541,-9.363) D37(-2.922,-9.363) D38(-3.485,-9.038) D39(-4.049,-9.363) D41(-5.43,-9.363) D42(-5.993,-9.038) D43(-6.556,-9.363) D45(-7.937,-9.363) D46(-8.5,-9.038) D47(-9.064,-9.363) D49(-10.444,-9.363) D50(-11.008,-9.038) D51(-11.571,-9.363) D53(-12.952,-9.363) D54(-13.515,-9.038) D55(-14.079,-9.363) D57(-15.459,-9.363) D58(-16.023,-9.038) D59(-16.586,-9.363) D60(-17.363,-9.513) D61(-18.014,-9.513) D62(-18.664,-9.28) E2(18.664,-8.589) E3(18.014,-8.627) E4(17.363,-8.627) E5(16.712,-8.695) E6(15.76,-8.695) E8(14.807,-8.695) E10(13.855,-8.695) E11(12.902,-8.695) E13(11.95,-8.695) E15(10.997,-8.695) E17(10.045,-8.695) E18(9.092,-8.695) E20(8.14,-8.695) E59(-16.713,-8.667) E60(-17.363,-8.667) E61(-18.014,-8.667) E62(-18.664,-8.629) F2(18.664,-7.84) F3(18.014,-7.802) F4(17.363,-7.802) F5(16.712,-8.045) F6(15.76,-8.045) F8(14.807,-8.045) F10(13.855,-8.045) F11(12.902,-8.045) F13(11.95,-8.045) F15(10.997,-8.045) F17(10.045,-8.045) F18(9.092,-8.045) F20(8.14,-8.045) F59(-16.713,-7.842) F60(-17.363,-7.842) F61(-18.014,-7.842) F62(-18.664,-7.88) F63(-19.314,-7.88) G1(19.314,-7.091) G2(18.664,-7.091) G3(18.014,-7.129) G4(17.363,-7.129) G5(16.712,-7.395) G6(15.76,-7.395) G8(14.807,-7.395) G10(13.855,-7.395) G11(12.902,-7.395) G13(11.95,-7.395) G15(10.997,-7.395) G17(10.045,-7.395) G18(9.092,-7.395) G20(8.14,-7.395) H5(16.712,-6.745) H6(15.76,-6.745) H8(14.807,-6.745) H10(13.855,-6.745) H11(12.902,-6.745) H13(11.95,-6.745) H15(10.997,-6.745) H17(10.045,-6.745) H18(9.092,-6.745) H20(8.14,-6.745) H59(-16.713,-7.169) H60(-17.363,-7.169) H61(-18.014,-7.169) H62(-18.664,-7.131) H63(-19.314,-7.131) J1(19.314,-6.341) J2(18.664,-6.341) J3(18.014,-6.303) J4(17.363,-6.303) J5(16.687,-6.094) J6(15.747,-6.094) J8(14.807,-6.094) J10(13.855,-6.094) J11(12.902,-6.094) J13(11.95,-6.094) J15(10.997,-6.094) J17(10.045,-6.094) J18(9.092,-6.094) J20(8.14,-6.094) J21(7.219,-6.328) J59(-16.713,-6.343) J60(-17.363,-6.343) J61(-18.014,-6.343) J62(-18.664,-6.381) J63(-19.314,-6.381) K1(19.314,-5.592) K2(18.664,-5.592) K3(18.014,-5.63) K4(17.363,-5.63) K59(-16.713,-5.67) K60(-17.363,-5.67) K61(-18.014,-5.67) K62(-18.664,-5.632) K63(-19.314,-5.632) L1(19.314,-4.843) L2(18.664,-4.843) L3(18.014,-4.805) L4(17.363,-4.805) L5(16.678,-4.977) L6(16.027,-4.977) L7(15.377,-4.977) L8(14.727,-4.977) L59(-16.713,-4.845) L60(-17.363,-4.845) L61(-18.014,-4.845) L62(-18.664,-4.883) L63(-19.314,-4.883) N1(19.314,-4.093) N2(18.664,-4.093) N3(18.014,-4.132) N4(17.363,-4.132) N5(16.678,-4.024) N6(16.027,-4.024) N7(15.377,-4.024) N8(14.727,-4.024) N59(-16.713,-4.172) N60(-17.363,-4.172) N61(-18.014,-4.172) N62(-18.664,-4.134) N63(-19.314,-4.134) P1(19.314,-3.344) P2(18.664,-3.344) P3(18.014,-3.306) P4(17.363,-3.306) P59(-16.713,-3.346) P60(-17.363,-3.346) P61(-18.014,-3.346) P62(-18.664,-3.384) P63(-19.314,-3.384) R5(16.678,-3.072) R6(16.027,-3.072) R7(15.377,-3.072) R8(14.727,-3.072) T1(19.314,-2.595) T2(18.664,-2.595) T3(18.014,-2.633) T4(17.363,-2.633) T59(-16.713,-2.673) T60(-17.363,-2.673) T61(-18.014,-2.673) T62(-18.664,-2.635) T63(-19.314,-2.635) U1(19.314,-1.846) U2(18.664,-1.846) U3(18.014,-1.807) U4(17.363,-1.807) U5(16.678,-2.119) U6(16.027,-2.119) U7(15.377,-2.119) U8(14.727,-2.119) U59(-16.713,-1.848) U60(-17.363,-1.848) U61(-18.014,-1.848) U62(-18.664,-1.886) U63(-19.314,-1.886) V1(19.314,-1.096) V2(18.664,-1.096) V3(18.014,-1.134) V4(17.363,-1.134) V5(16.678,-1.167) V6(16.027,-1.167) V7(15.377,-1.167) V8(14.727,-1.167) V59(-16.713,-1.174) V60(-17.363,-1.174) V61(-18.014,-1.174) V62(-18.664,-1.136) V63(-19.314,-1.136) Y1(19.314,-0.347) Y2(18.664,-0.347) Y3(18.014,-0.309) Y4(17.363,-0.309) Y5(16.678,-0.214) Y6(16.027,-0.214) Y7(15.377,-0.214) Y8(14.727,-0.214) Y59(-16.713,-0.349) Y60(-17.363,-0.349) Y61(-18.014,-0.349) Y62(-18.664,-0.387) Y63(-19.314,-0.387)
  round 0.33 smd: AK22(6.659,4.952) AK23(5.786,4.952) AK25(4.81,4.952) AK26(3.858,4.952) AK28(2.905,4.952) AK29(2.004,4.952) AK32(0.49,4.952) AK33(-0.412,4.952) AK35(-1.415,4.952) AK36(-2.266,4.952) AK38(-3.295,4.952) AK40(-4.792,4.952) AK42(-5.63,4.952) AK43(-6.582,4.952) AK45(-7.56,4.952) AK46(-8.462,4.952) AK48(-9.516,4.952) AK49(-10.418,4.952) AK51(-11.421,4.952) AK52(-12.269,4.952) AK54(-13.295,4.952) AK55(-14.248,4.952) AK57(-15.195,4.952) AK58(-16.094,4.952)
